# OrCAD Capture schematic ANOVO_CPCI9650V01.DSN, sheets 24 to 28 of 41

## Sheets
24 -IDE slot & COM1 2: size C; title: 24--IDE,CF slot
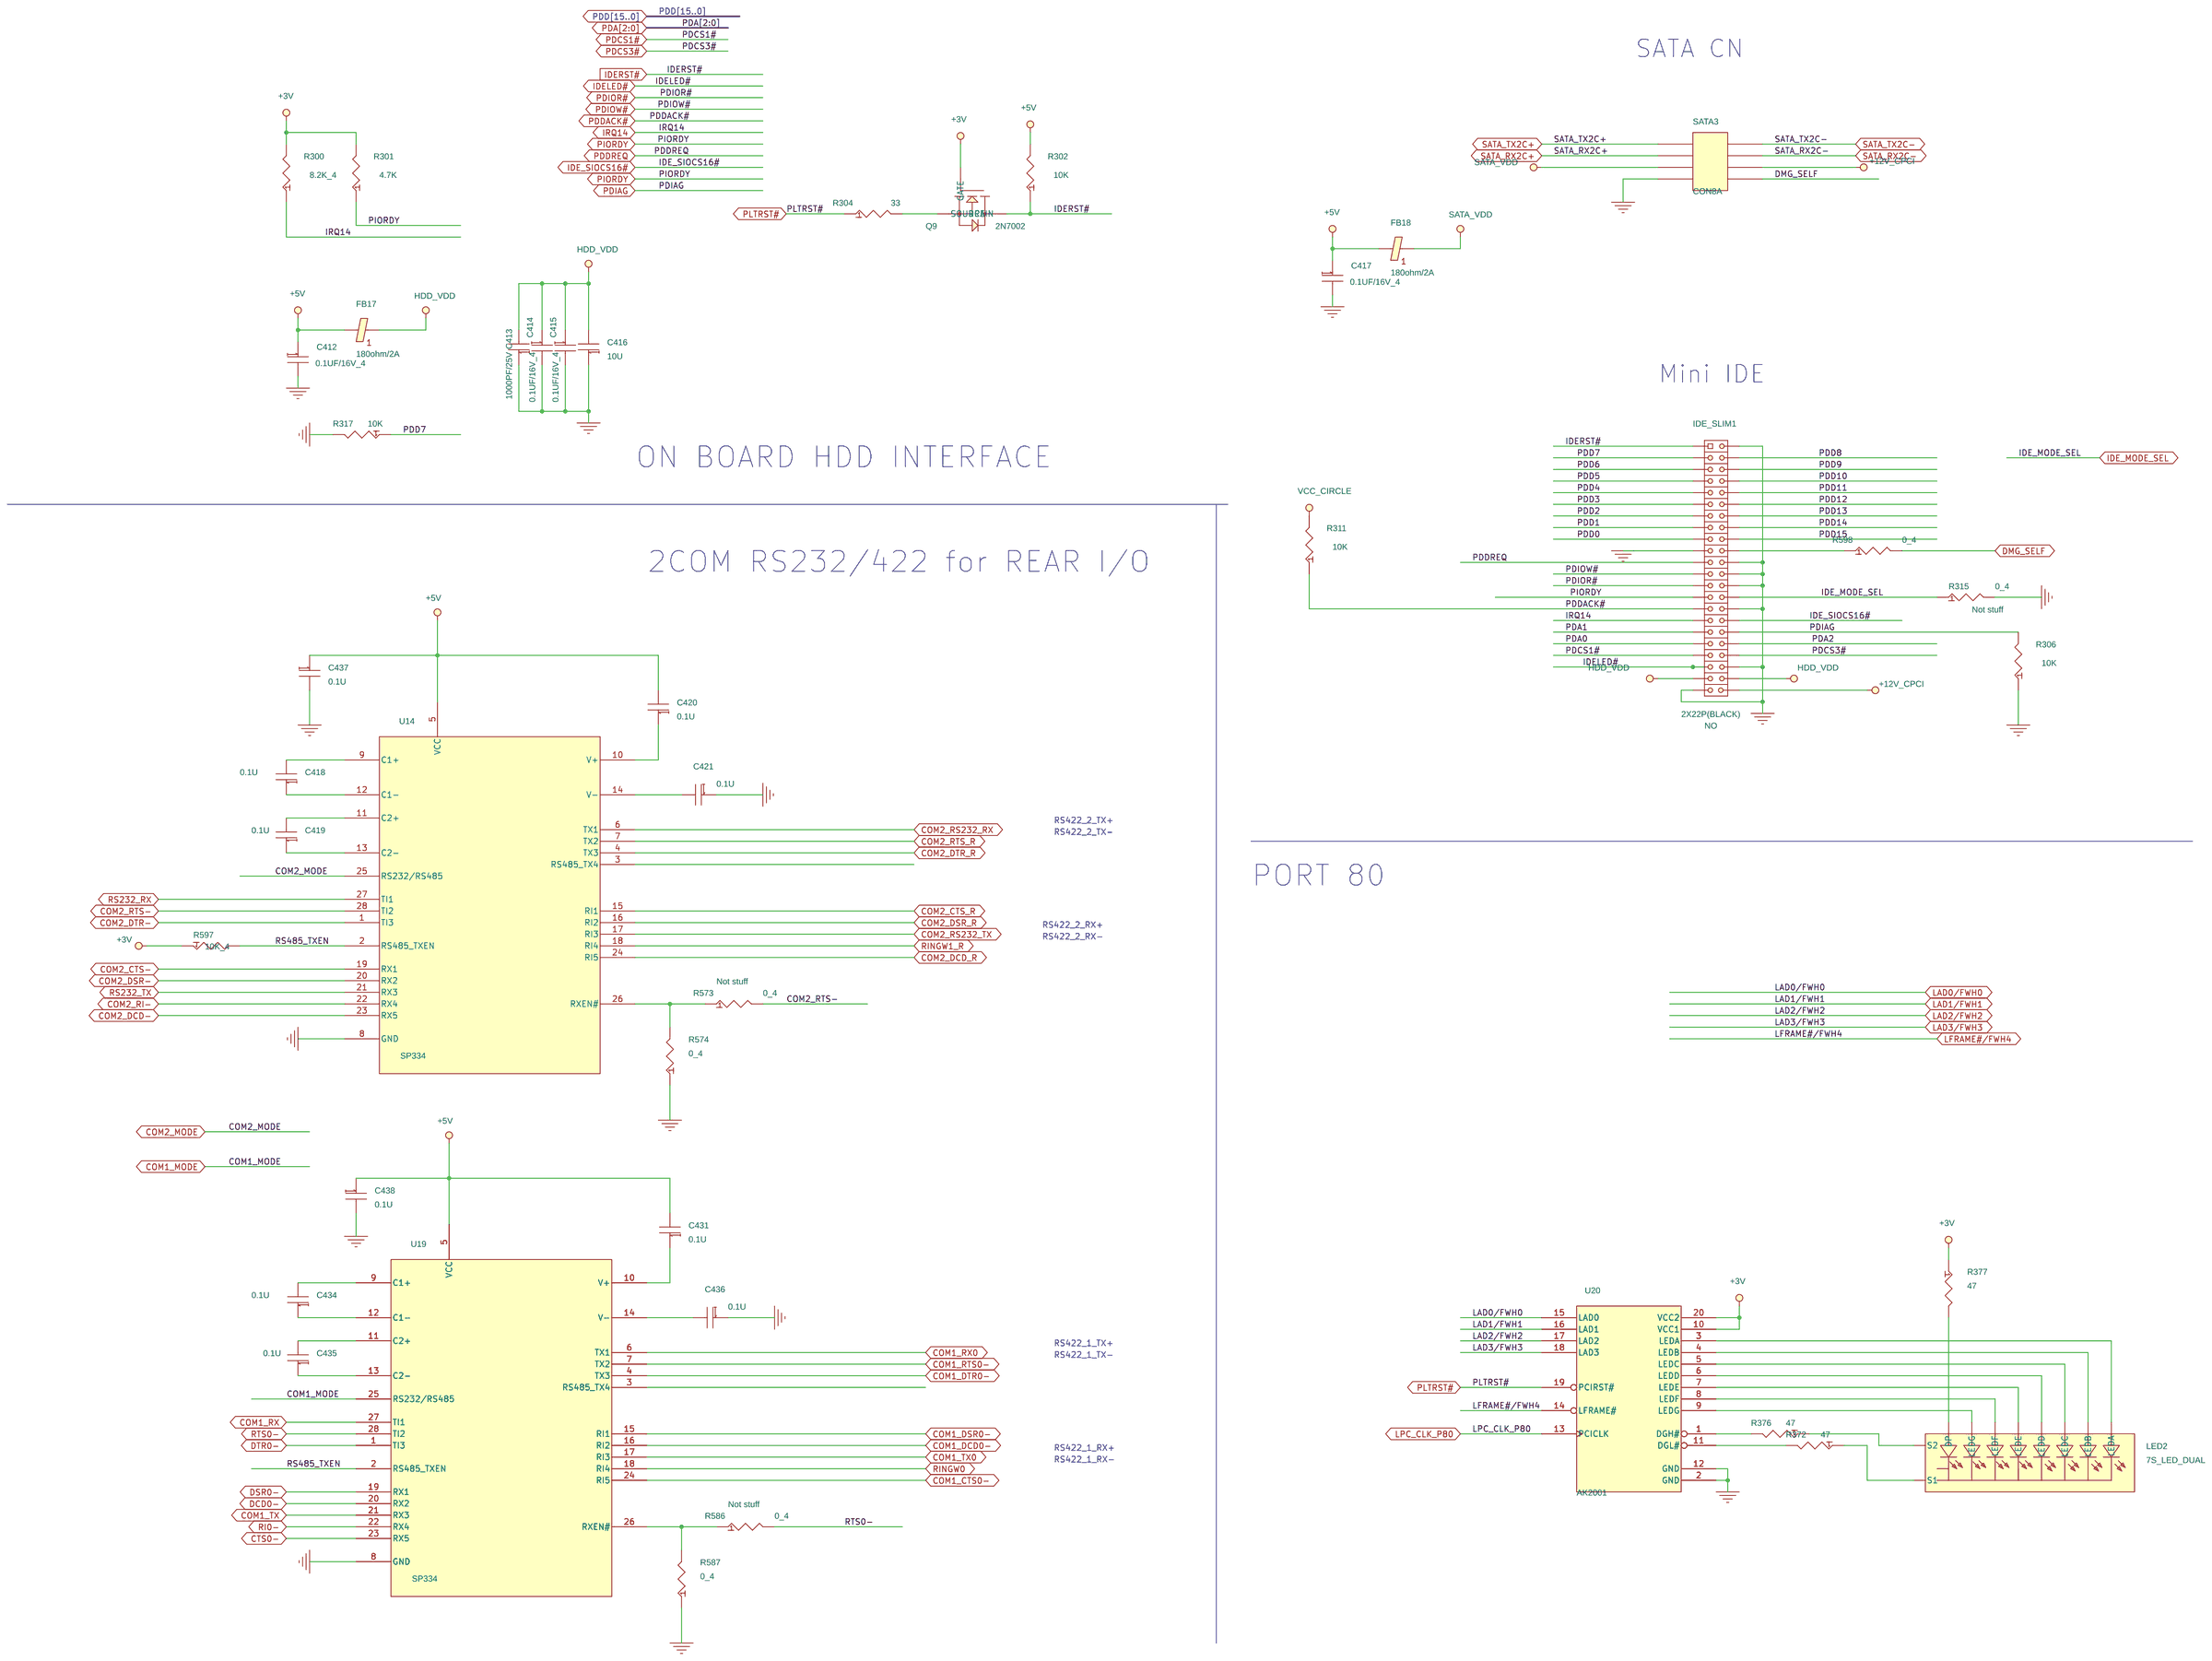
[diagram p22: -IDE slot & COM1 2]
25 -PWRBTN &LVDS VCC: size C; title: 25--SIO_W83627THF
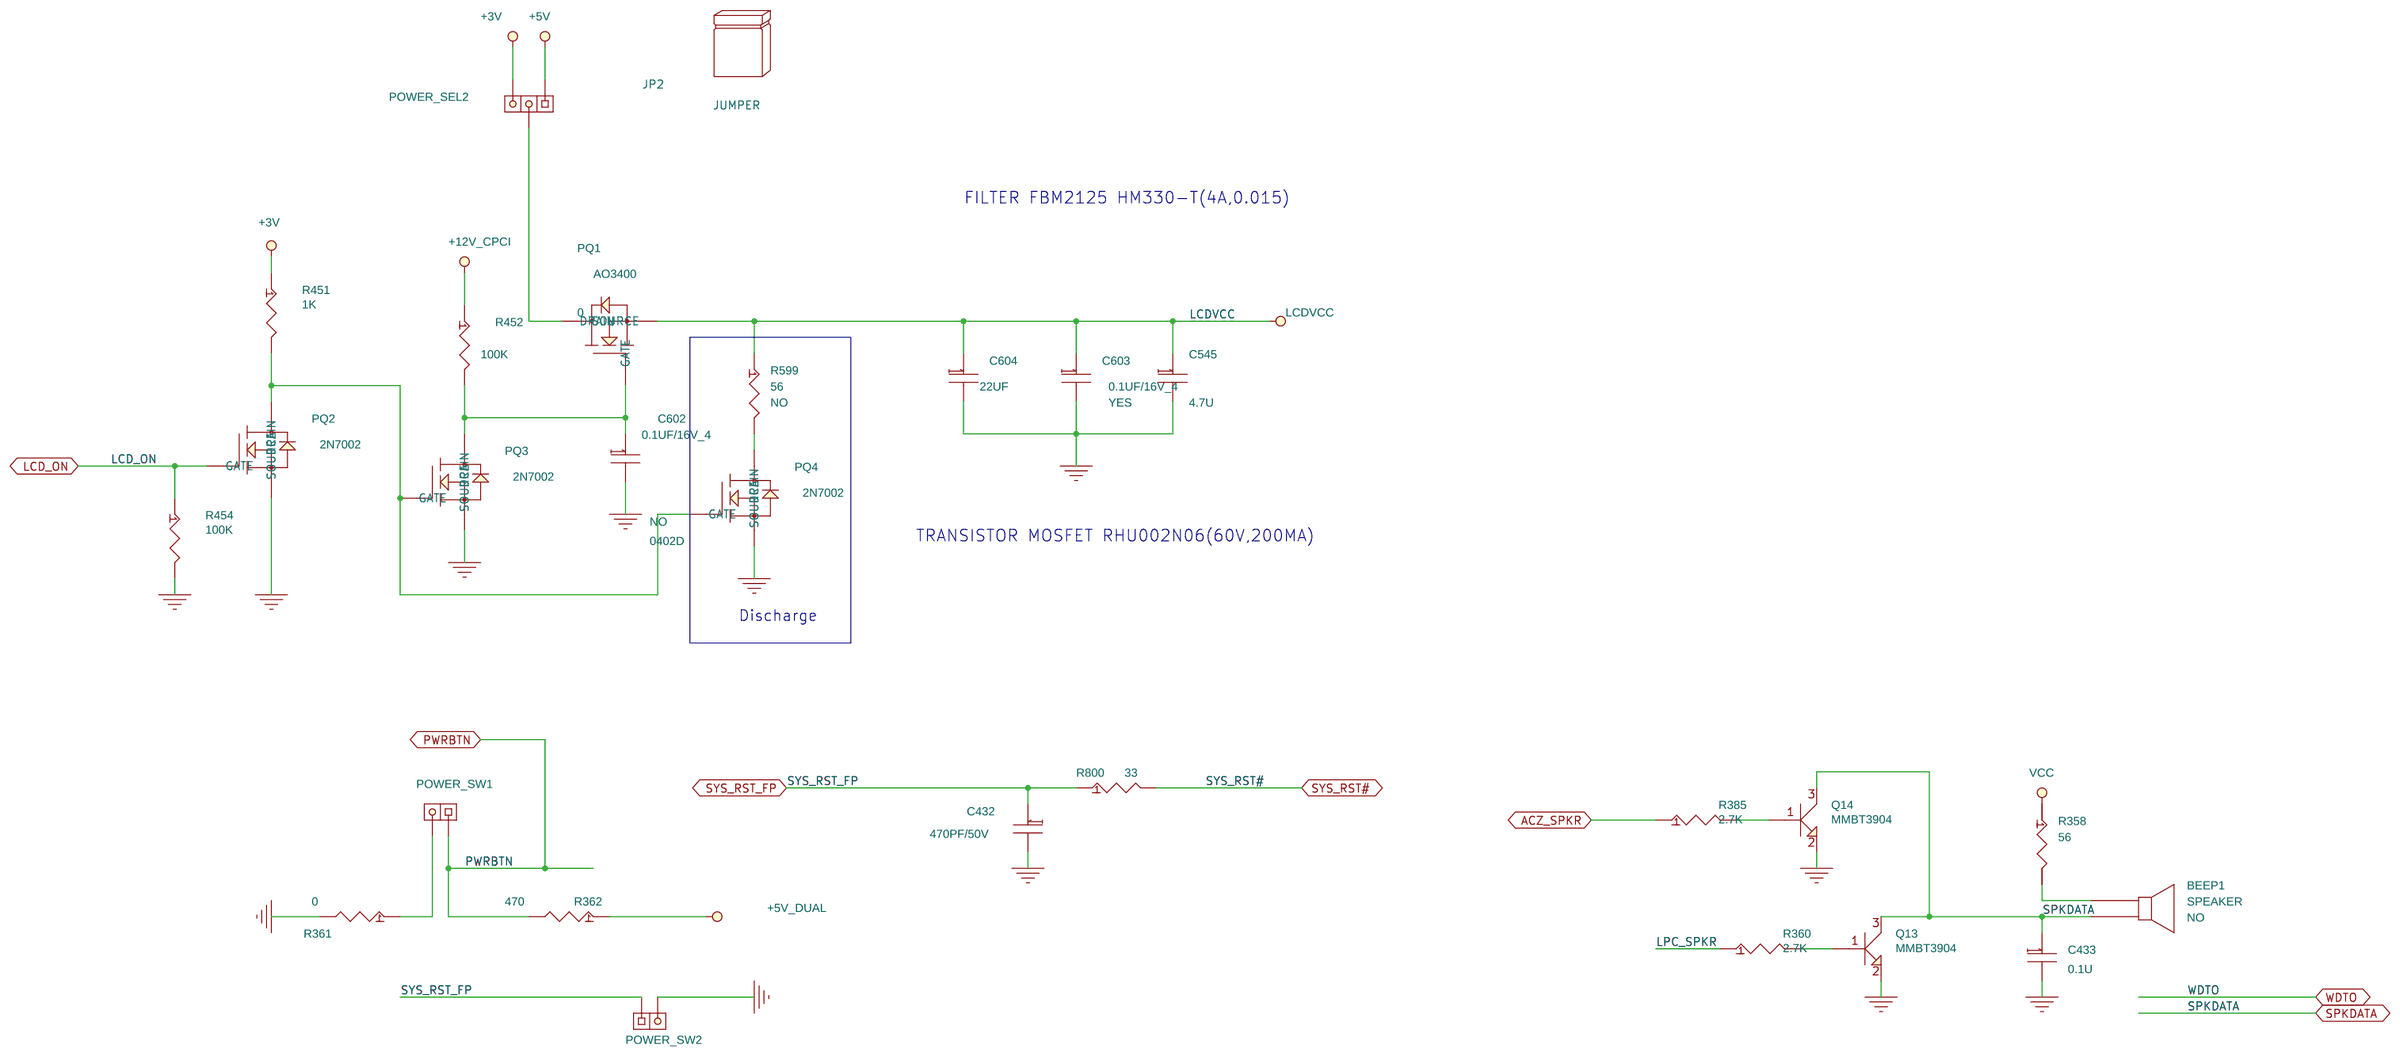
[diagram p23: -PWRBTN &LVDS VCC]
26 -VGA SWITCHS&PIO&WTO: size D; title: 26--VGA swtich&PIO; note: CPCI965
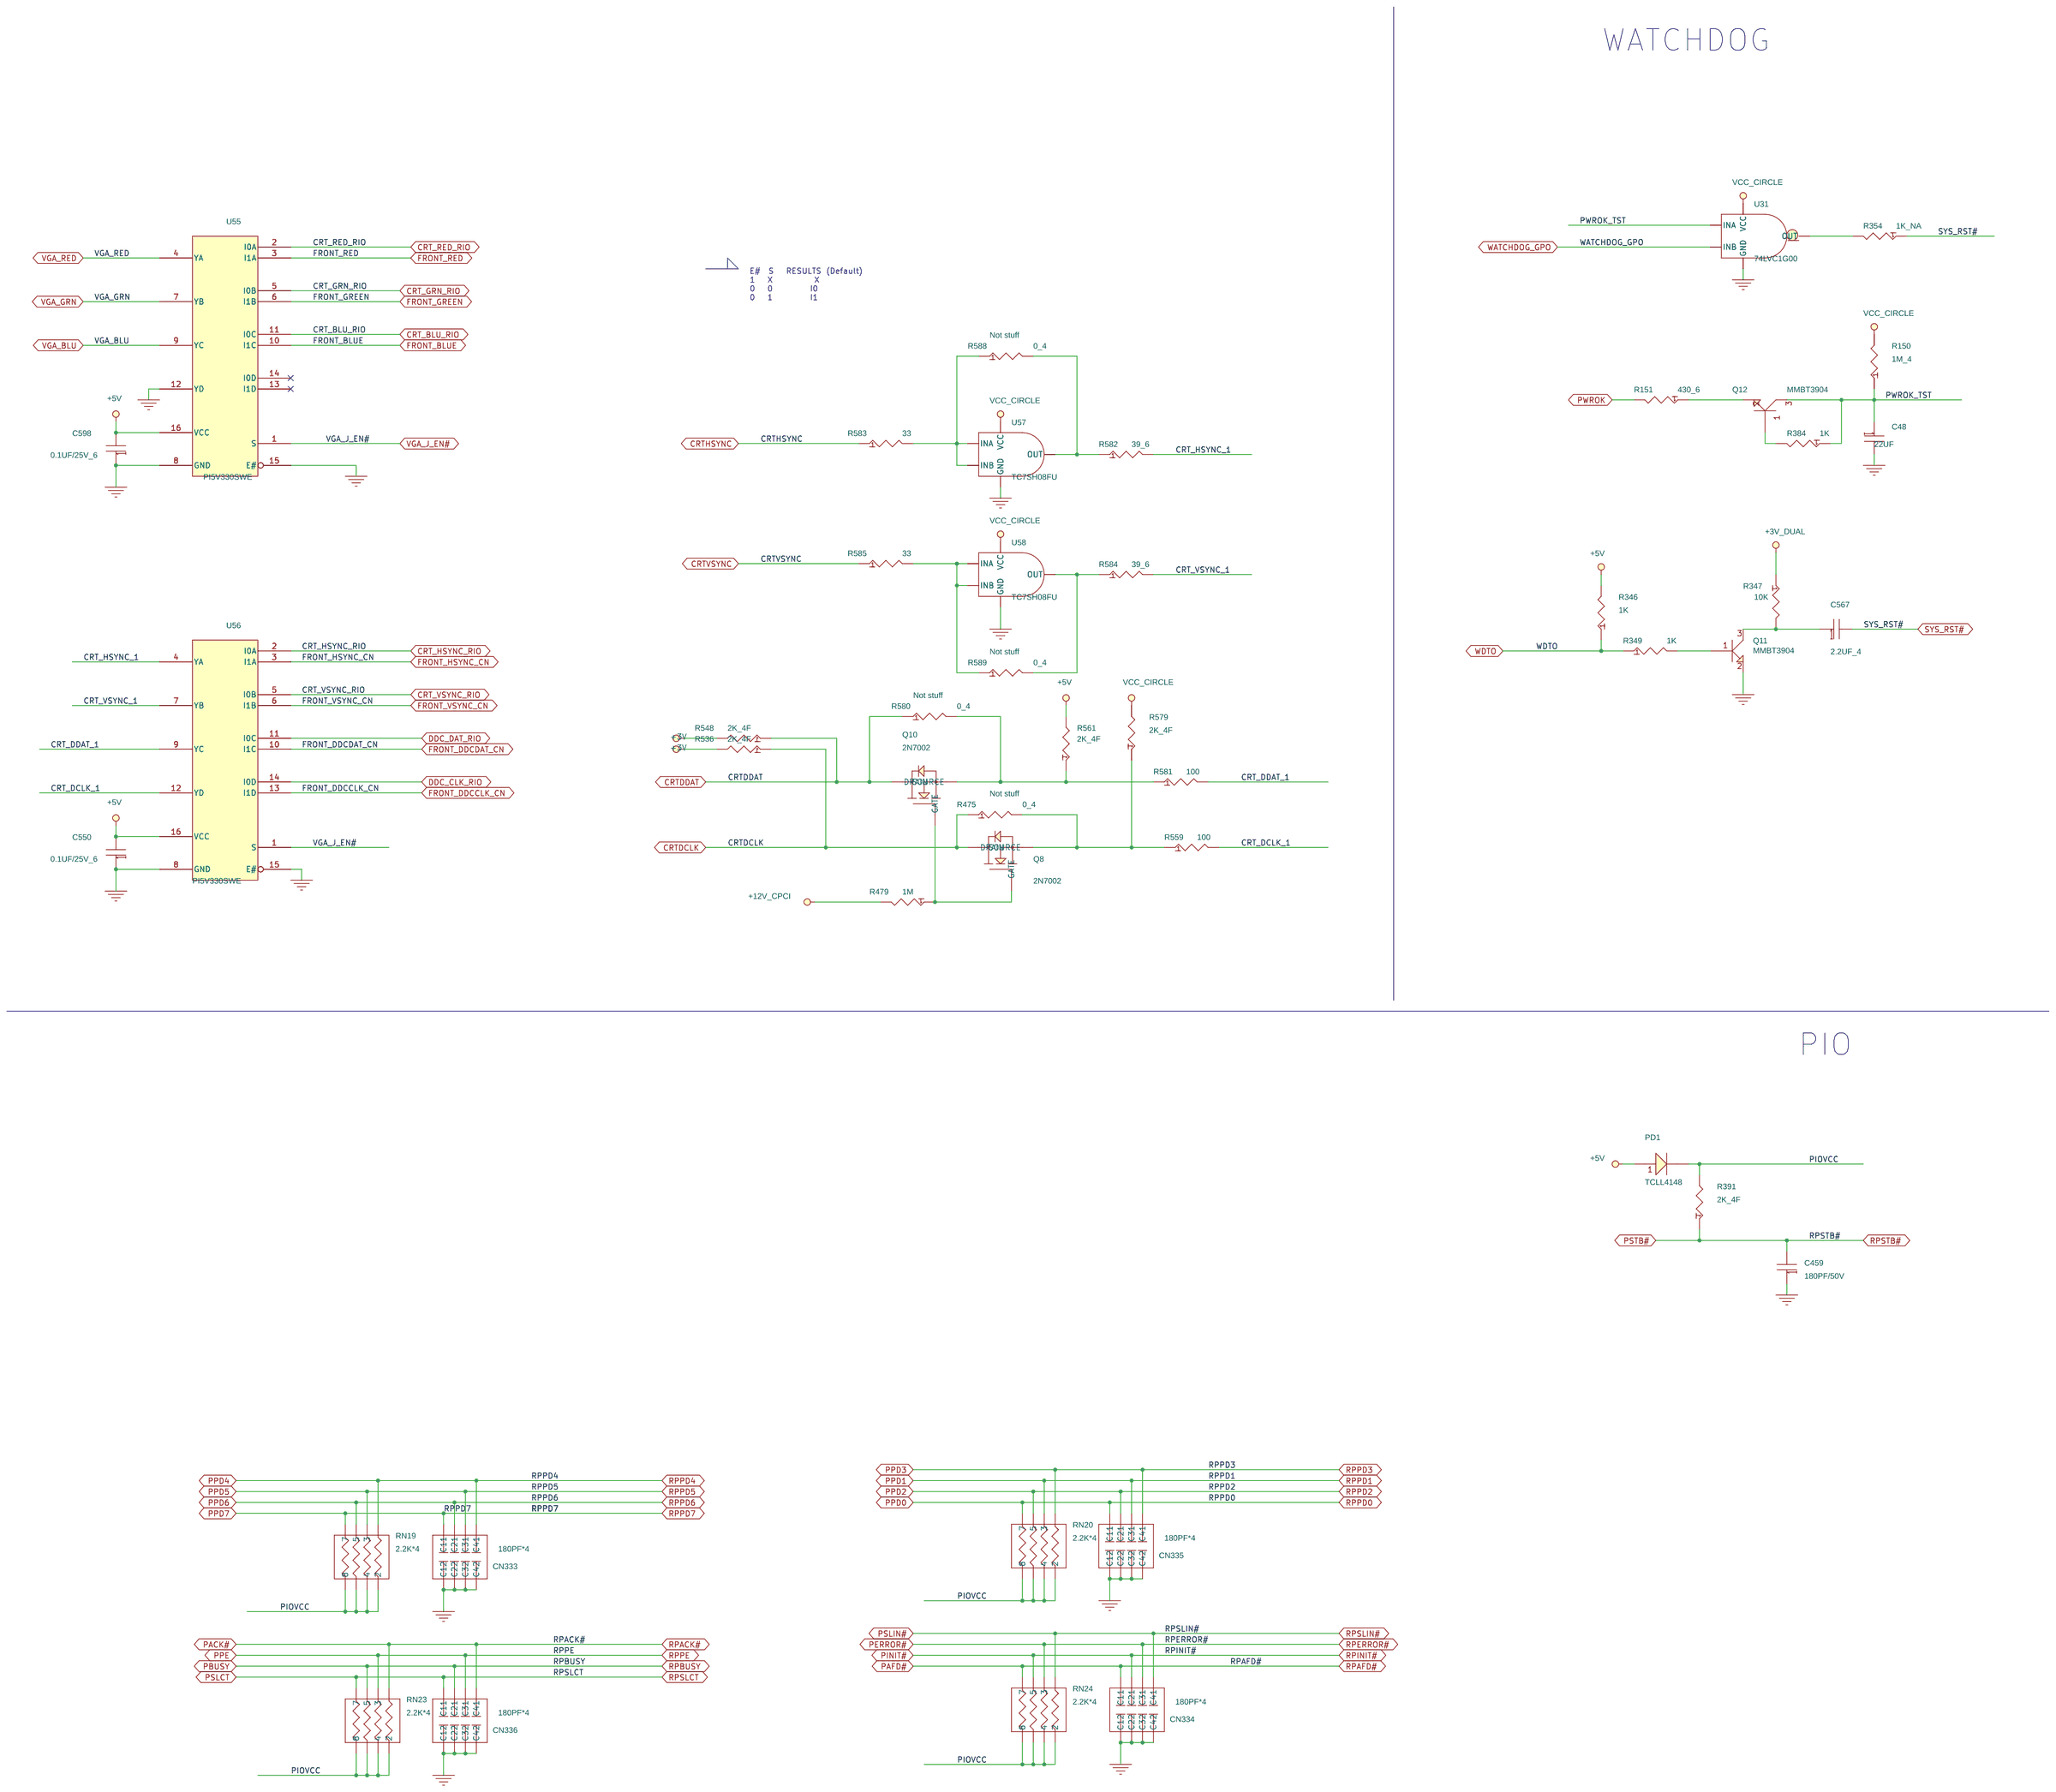
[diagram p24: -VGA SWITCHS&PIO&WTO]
27 -J1 PCI32&BRIDGE: size C; title: 27--J1 PCI32
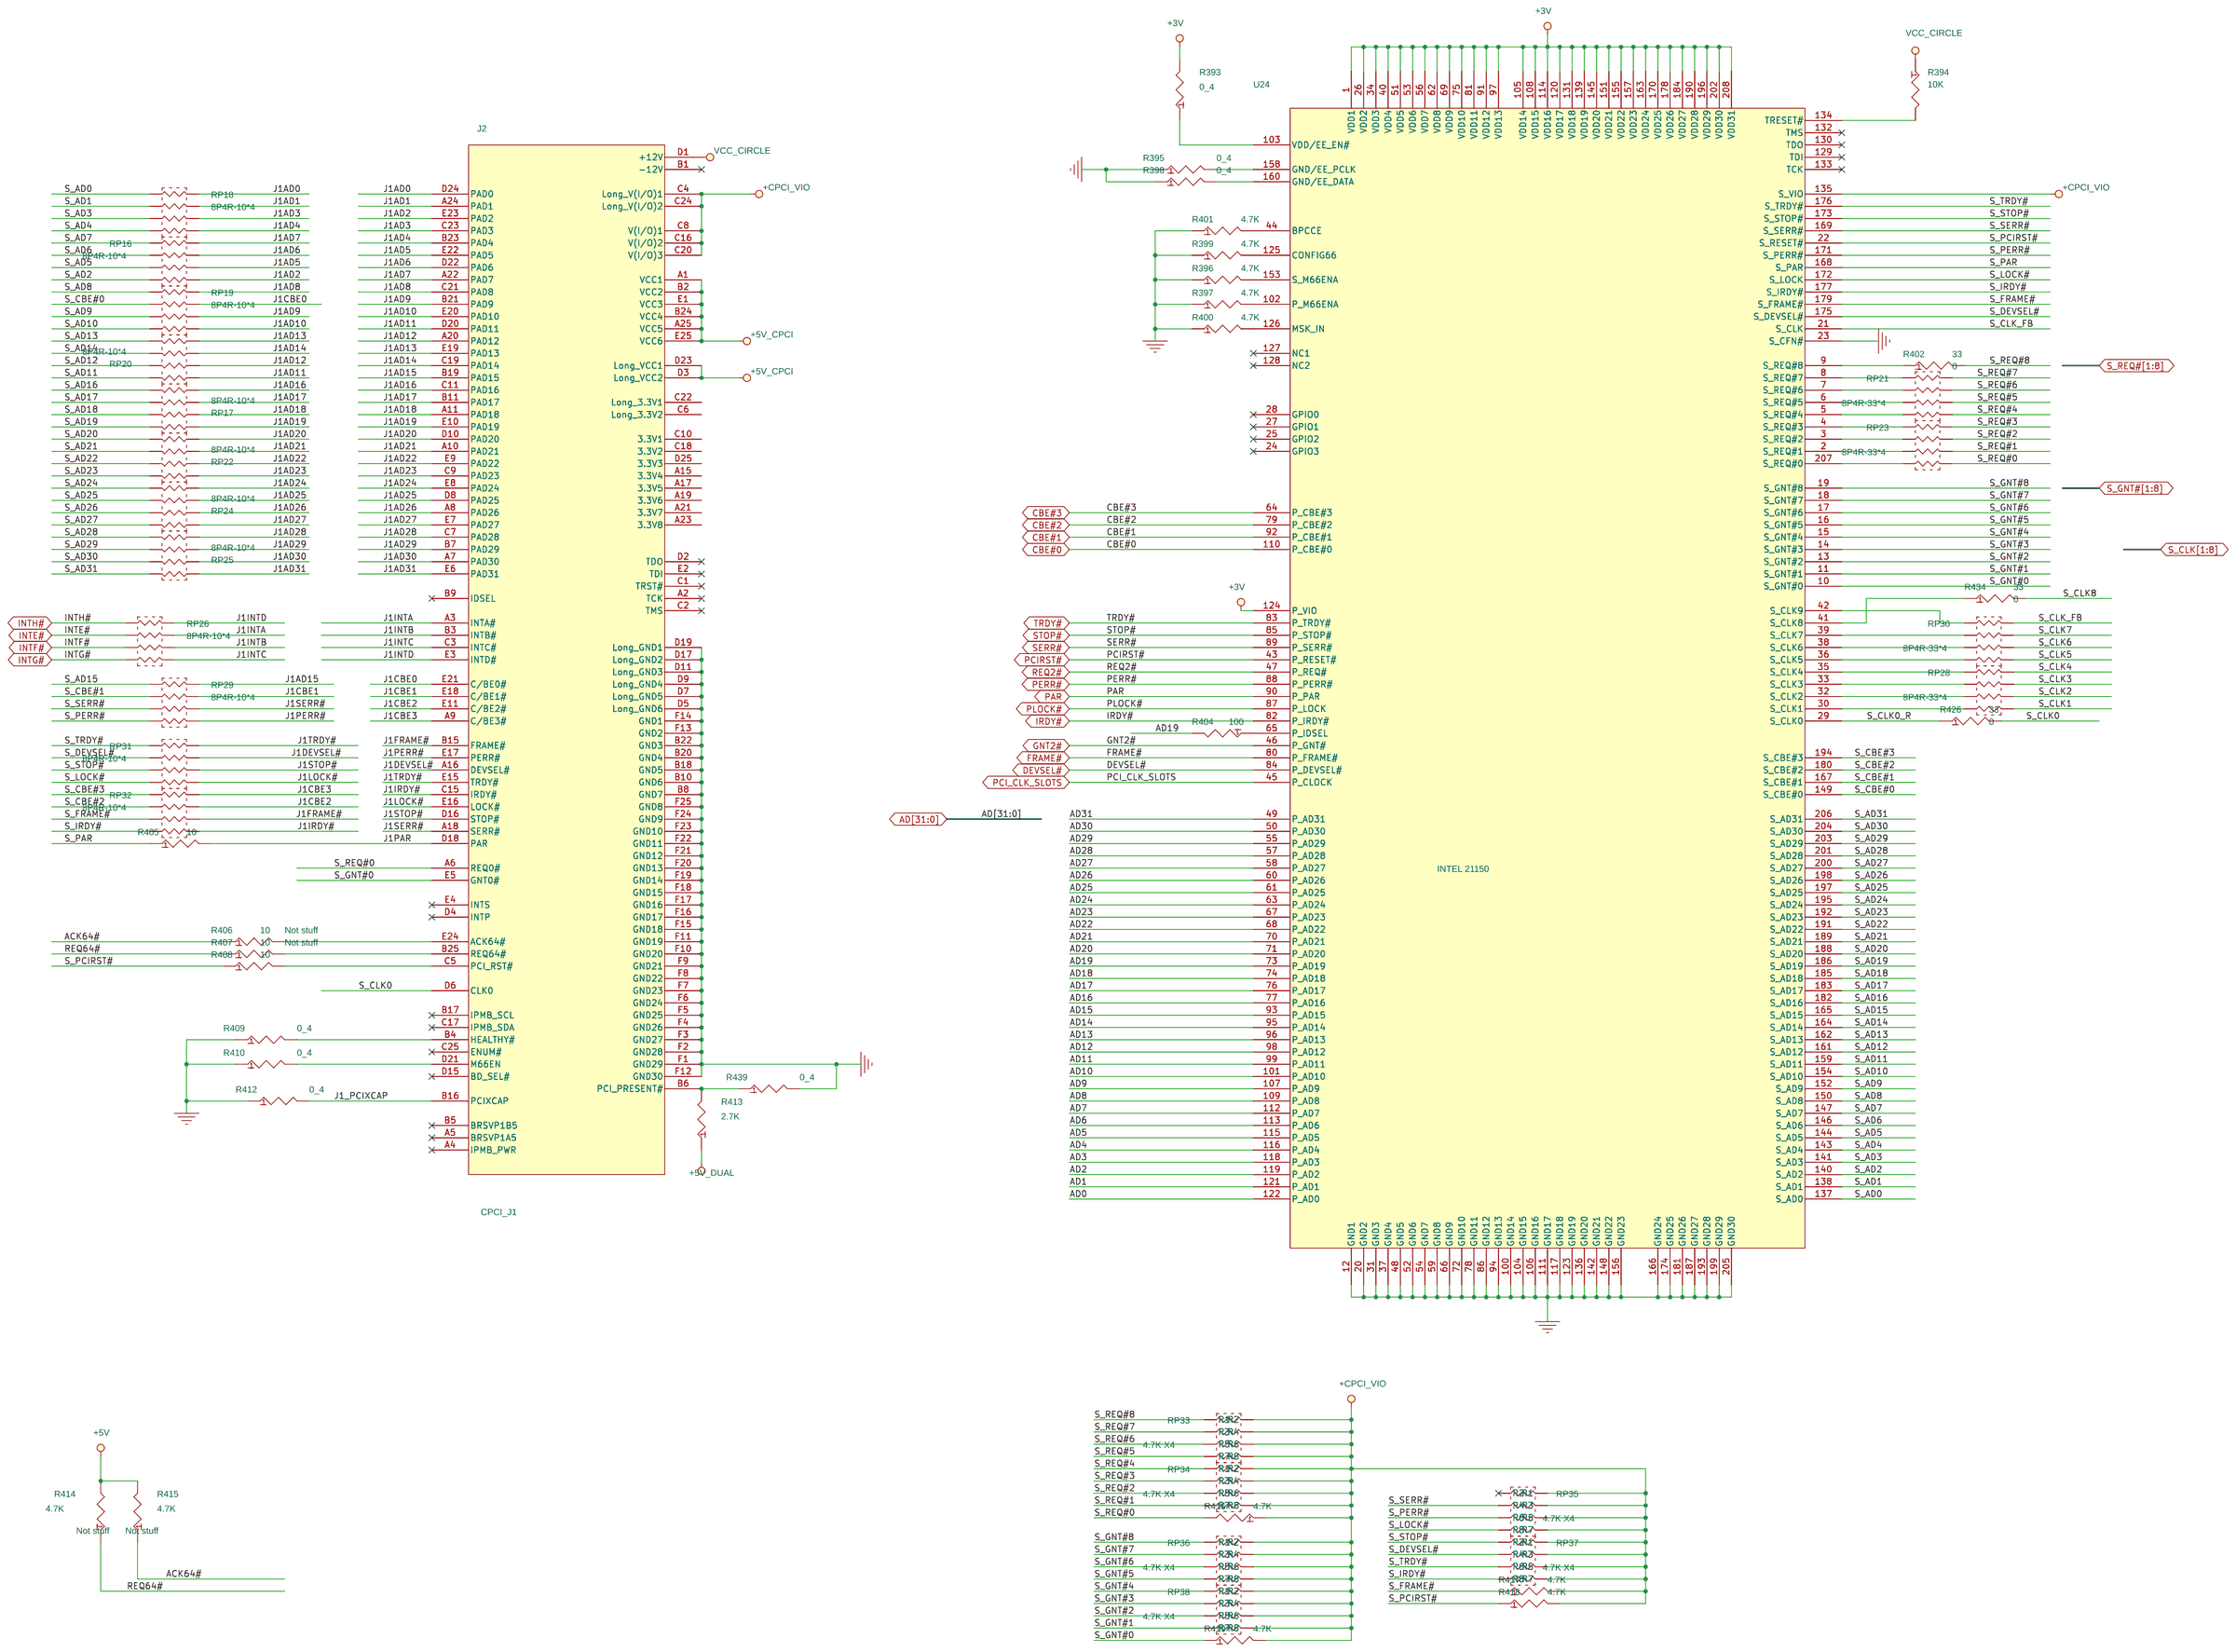
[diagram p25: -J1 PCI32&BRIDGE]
28 -J2 J3 PCIE: size C; title: 28--J2 J3 PCIE
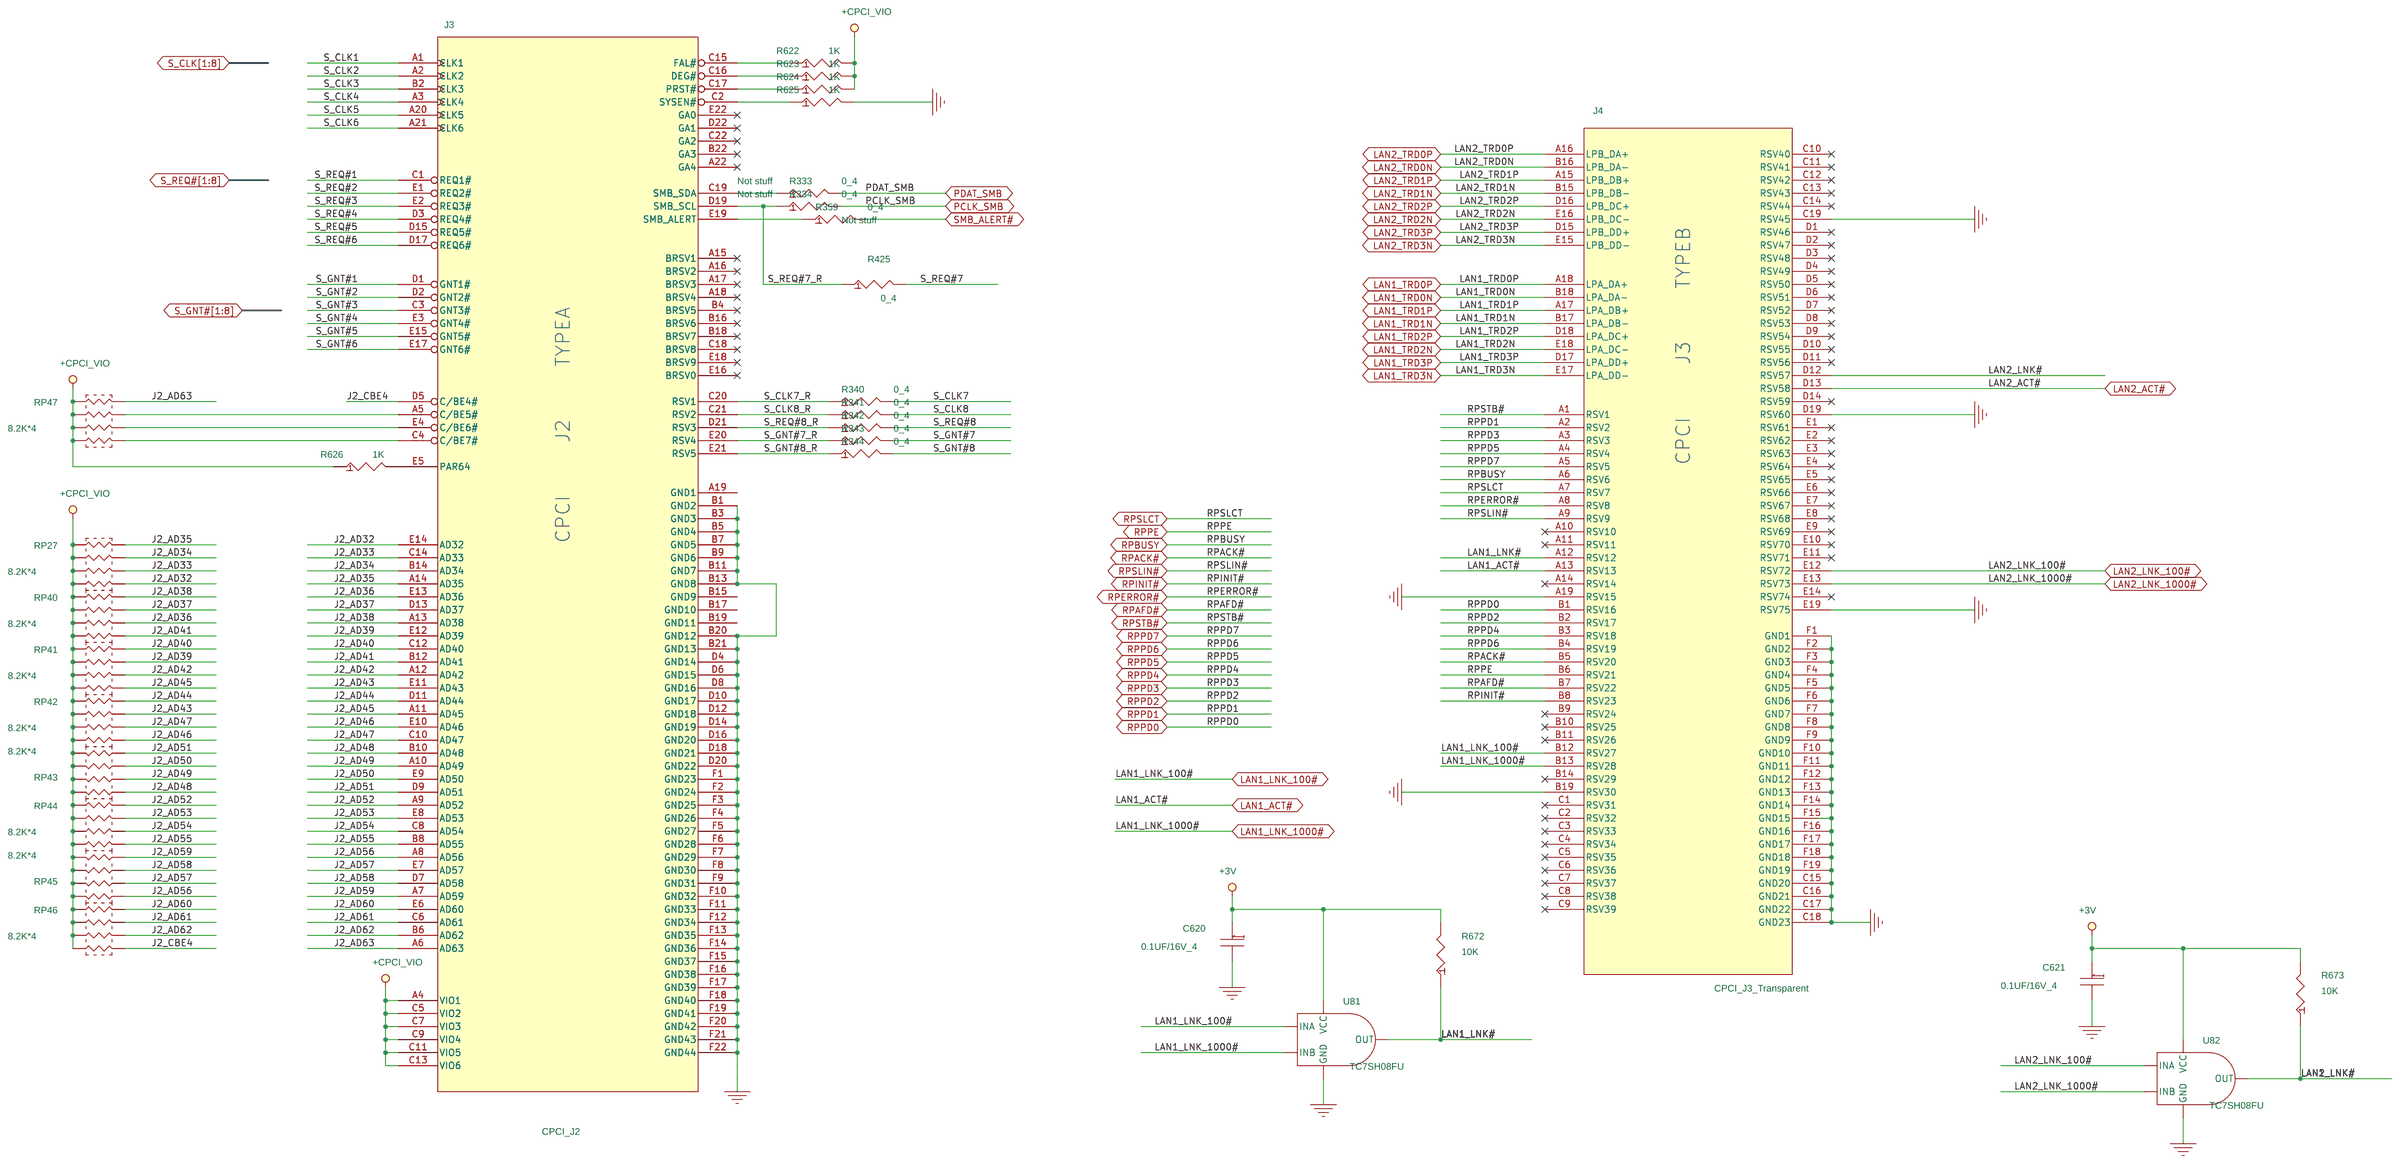
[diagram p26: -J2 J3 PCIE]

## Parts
sheet -IDE slot & COM1 2
C412  0.1UF/16V_4  [0402D]
C413  1000PF/25V  [0402D]
C414  0.1UF/16V_4  [0402D]
C415  0.1UF/16V_4  [0402D]
C416  10U  [0805D]
C417  0.1UF/16V_4  [0402D]
C418  0.1U  [0402D]
C419  0.1U  [0402D]
C420  0.1U  [0402D]
C421  0.1U  [0402D]
C431  0.1U  [0402D]
C434  0.1U  [0402D]
C435  0.1U  [0402D]
C436  0.1U  [0402D]
C437  0.1U  [0402D]
C438  0.1U  [0402D]
FB17  180ohm/2A  [0805D]
FB18  180ohm/2A  [0805D]
IDE_SLIM1  2X22P(BLACK)  [IDE_S]
LED2  7S_LED_DUAL  [LEDX2_2R54X7R62_15X10]
Q9  2N7002  [SOT23N_5]
R300  8.2K_4  [0402D]
R301  4.7K  [0402D]
R302  10K  [0402D]
R304  33  [0402D]
R306  10K  [0402D]
R311  10K  [0402D]
R315  0_4  [0402D]
R317  10K  [0402D]
R372  47  [0603D]
R376  47  [0603D]
R377  47  [0603D]
R573  0_4  [0402D]
R574  0_4  [0402D]
R586  0_4  [0402D]
R587  0_4  [0402D]
R597  10K_4  [0402D]
R598  0_4  [0402D]
SATA3  CON8A  [conn_2x4_2mm]
U14  SP334  [soic_28p_26_706x419]
U19  SP334  [soic_28p_26_706x419]
U20  AK2001  [ssop20_0r64_8r64x5r99]
sheet -J1 PCI32&BRIDGE
J2  CPCI_J1  [conn_cpci25x5_p13]
R393  0_4  [0402D]
R394  10K  [0402D]
R395  0_4  [0402D]
R396  4.7K  [0402D]
R397  4.7K  [0402D]
R398  0_4  [0402D]
R399  4.7K  [0402D]
R400  4.7K  [0402D]
R401  4.7K  [0402D]
R402  33  [0402D]
R404  100  [0402D]
R405  10  [0402D]
R406  10  [0402D]
R407  10  [0402D]
R408  10  [0402D]
R409  0_4  [0402D]
R410  0_4  [0402D]
R412  0_4  [0402D]
R413  2.7K  [0402D]
R414  4.7K  [0402D]
R415  4.7K  [0402D]
R416  4.7K  [0402D]
R417  4.7K  [0402D]
R418  4.7K  [0402D]
R419  4.7K  [0402D]
R426  33  [0402D]
R434  33  [0402D]
R439  0_4  [0402D]
RP16  8P4R-10*4  [RP_8P4R_0804B]
RP17  8P4R-10*4  [RP_8P4R_0804B]
RP18  8P4R-10*4  [RP_8P4R_0804B]
RP19  8P4R-10*4  [RP_8P4R_0804B]
RP20  8P4R-10*4  [RP_8P4R_0804B]
RP21  8P4R-33*4  [RP_8P4R_0804B]
RP22  8P4R-10*4  [RP_8P4R_0804B]
RP23  8P4R-33*4  [RP_8P4R_0804B]
RP24  8P4R-10*4  [RP_8P4R_0804B]
RP25  8P4R-10*4  [RP_8P4R_0804B]
RP26  8P4R-10*4  [RP_8P4R_0804B]
RP28  8P4R-33*4  [RP_8P4R_0804B]
RP29  8P4R-10*4  [RP_8P4R_0804B]
RP30  8P4R-33*4  [RP_8P4R_0804B]
RP31  8P4R-10*4  [RP_8P4R_0804B]
RP32  8P4R-10*4  [RP_8P4R_0804B]
RP33  4.7K X4  [RPSOA_8C]
RP34  4.7K X4  [RPSOA_8C]
RP35  4.7K X4  [RPSOA_8C]
RP36  4.7K X4  [RPSOA_8C]
RP37  4.7K X4  [RPSOA_8C]
RP38  4.7K X4  [RPSOA_8C]
U24  INTEL 21150  [PQFP208A]
sheet -J2 J3 PCIE
C620  0.1UF/16V_4  [0402D]
C621  0.1UF/16V_4  [0402D]
J3  CPCI_J2  [conn_cpci22x5_p11]
J4  CPCI_J3_Transparent  [conn_cpci19x5_p10]
R333  0_4  [0402D]
R334  0_4  [0402D]
R340  0_4  [0402D]
R341  0_4  [0402D]
R342  0_4  [0402D]
R343  0_4  [0402D]
R344  0_4  [0402D]
R359  0_4  [0402D]
R425  0_4  [0402D]
R622  1K  [0402D]
R623  1K  [0402D]
R624  1K  [0402D]
R625  1K  [0402D]
R626  1K  [0402D]
R672  10K  [0402D]
R673  10K  [0402D]
RP27  8.2K*4  [RP_8P4R_0804B]
RP40  8.2K*4  [RP_8P4R_0804B]
RP41  8.2K*4  [RP_8P4R_0804B]
RP42  8.2K*4  [RP_8P4R_0804B]
RP43  8.2K*4  [RP_8P4R_0804B]
RP44  8.2K*4  [RP_8P4R_0804B]
RP45  8.2K*4  [RP_8P4R_0804B]
RP46  8.2K*4  [RP_8P4R_0804B]
RP47  8.2K*4  [RP_8P4R_0804B]
U81  TC7SH08FU  [SSOP5_TOSHIBA]
U82  TC7SH08FU  [SSOP5_TOSHIBA]
sheet -PWRBTN &LVDS VCC
BEEP1  SPEAKER  [BUZ_CB9E]
C432  470PF/50V  [0402D]
C433  0.1U  [0402D]
C545  4.7U  [0805D]
C602  0.1UF/16V_4  [0402D]
C603  0.1UF/16V_4  [0402D]
C604  22UF  [0805D]
JP2  JUMPER
POWER_SEL2  1x3 PIN  [conn_3b]
POWER_SW1  1x2 PIN  [CONN_2B]
POWER_SW2  1x2 PIN  [CONN_2B]
PQ1  AO3400  [SOT23N_5]
PQ2  2N7002  [SOT23N_5]
PQ3  2N7002  [SOT23N_5]
PQ4  2N7002  [SOT23N_5]
Q13  MMBT3904  [SOT23N_5]
Q14  MMBT3904  [SOT23N_5]
R358  56  [0603D]
R360  2.7K  [0402D]
R361  0  [0402D]
R362  470  [0402D]
R385  2.7K  [0402D]
R451  1K  [0402D]
R452  100K  [0402D]
R454  100K  [0402D]
R599  56  [0603D]
R800  33  [0402D]
sheet -VGA SWITCHS&PIO&WTO
C48  22UF  [0805D]
C459  180PF/50V  [0402D]
C550  0.1UF/25V_6  [0603D]
C567  2.2UF_4  [0402D]
C598  0.1UF/25V_6  [0603D]
CN333  180PF*4  [RPSOA_8D]
CN334  180PF*4  [RPSOA_8D]
CN335  180PF*4  [RPSOA_8D]
CN336  180PF*4  [RPSOA_8D]
PD1  TCLL4148  [DC1506N]
Q8  2N7002  [SOT23N_5]
Q10  2N7002  [SOT23N_5]
Q11  MMBT3904  [SOT23N_5]
Q12  MMBT3904  [SOT23N_5]
R150  1M_4  [0402D]
R151  430_6  [0603D]
R346  1K  [0402D]
R347  10K  [0402D]
R349  1K  [0402D]
R354  1K_NA  [0402D]
R384  1K  [0402D]
R391  2K_4F  [0402D]
R475  0_4  [0402D]
R479  1M  [0603D]
R536  2K_4F  [0402D]
R548  2K_4F  [0402D]
R559  100  [0402D]
R561  2K_4F  [0402D]
R579  2K_4F  [0402D]
R580  0_4  [0402D]
R581  100  [0402D]
R582  39_6  [0603D]
R583  33  [0402D]
R584  39_6  [0603D]
R585  33  [0402D]
R588  0_4  [0402D]
R589  0_4  [0402D]
RN19  2.2K*4  [RPSOA_8C]
RN20  2.2K*4  [RPSOA_8C]
RN23  2.2K*4  [RPSOA_8C]
RN24  2.2K*4  [RPSOA_8C]
U31  74LVC1G00  [SSOP5_TOSHIBA]
U55  PI5V330SWE  [SOIC16]
U56  PI5V330SWE  [SOIC16]
U57  TC7SH08FU  [SSOP5_TOSHIBA]
U58  TC7SH08FU  [SSOP5_TOSHIBA]

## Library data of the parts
C412 C414 C415 C417 C620 C621 = CAP_NP: ANOVO DESCRIPTION: CAP;0.1U ,16V ,+80-20% ,0402 ,Y5V ,SMT; ANOVO PART NUMBER: 272043104401; BACKSIDE: 0; Part Type: CCAP; SMT: YES
C413 = CAP_NP: ANOVO DESCRIPTION: CAP;1000P ,16V ,10% ,0402 ,X7R ,SMT; ANOVO PART NUMBER: 272043102201; BACKSIDE: 0; Part Type: CCAP
C416 = CAP_NP: ANOVO DESCRIPTION: CAP;10U,10V,+80-20%,0805,Y5V,SMT; ANOVO PART NUMBER: 272002106401; Part Type: CCAP
C418-C421 C431 C433-C438 = CAP_NP: ANOVO DESCRIPTION: CAP;0.1U ,16V ,10% ,0402 ,X7R ,SMT; ANOVO PART NUMBER: 272043104201; Part Type: CCAP
FB17 FB18 = FERRITE_BEAD: ANOVO DESCRIPTION: FERRITE CHIP;180 OHM/100MHZ,2A,0805,SMT; ANOVO PART NUMBER: 273001814300; BACKSIDE: 0; Part Type: FERRITE BEAD; SMT: YES
IDE_SLIM1 = HEADER_2X20_0: ANOVO DESCRIPTION: CON,DIP,HDR,W/Shield,Black,22P*2,2.00*2.00mm pitch,ST,Slim IDE,Gold,Lotes; ANOVO PART NUMBER: 331120044100; BACKCOMP: NO; BACKSIDE: NO; Part Number: 131000064; Part Type: HEADER; ROOM: IDE; SMT: NO
LED2 = 7Seg_LED_0: ANOVO DESCRIPTION: CON;DIP,DISPLAY MODULE,7SEG,0.28INCH,GREEN,COMMON CATHODE,BD-F282RD,LIGITEK; ANOVO PART NUMBER: 331520010000
PQ2-PQ4 Q8-Q10 = MOSFET_N_3P: ANOVO DESCRIPTION: TRANS;2N7002,N-MOSFET,60V,500mA,SOT23; ANOVO PART NUMBER: 288227002001; BACKSIDE: 0; Part Type: MOSFET; SMT: YES
R300 = R_v2: ANOVO DESCRIPTION: RES;8.2K ,1/16W ,5% ,0402 ,SMT; ANOVO PART NUMBER: 271040822301; BACKSIDE: 0; Part Type: RESISTOR; SMT: YES
R301 R396 R397 R399-R401 R416-R419 = R_v2: ANOVO DESCRIPTION: RES;4.7K ,1/16W ,5% ,0402 ,SMT; ANOVO PART NUMBER: 271040472301; Part Type: RESISTOR
R302 R306 R311 R317 R347 R672 R673 = R_v2: ANOVO DESCRIPTION: RES;10K ,1/16W ,5% ,0402 ,SMT; ANOVO PART NUMBER: 271040103301; BACKSIDE: 0; Part Type: RESISTOR; SMT: YES
R304 R402 R426 R434 R583 R585 = R_v2: ANOVO DESCRIPTION: RES;33 ,1/16W ,5% ,0402 ,SMT; ANOVO PART NUMBER: 271040330301; BACKSIDE: 0; Part Type: RESISTOR; SMT: YES
R315 R573 R586 = R_v2: ANOVO DESCRIPTION: RES;0 ,1/16W ,5% ,0402 ,SMT; ANOVO PART NUMBER: 271040000301; DUMMY: Not stuff; Part Type: RESISTOR; SMT: YES
R372 R376 R377 = R_v2: RES;47 ,1/10W ,1% ,0603 ,SMT; ANOVO DESCRIPTION: RES;47 ,1/10W ,1% ,0603 ,SMT; ANOVO PART NUMBER: 271071470101; BACKCOMP: YES; Part Type: RESISTOR; SMT: YES
R361 R393 R409 R410 R412 R439 R574 R587 R598 = R_v2: ANOVO DESCRIPTION: RES;0 ,1/16W ,5% ,0402 ,SMT; ANOVO PART NUMBER: 271040000301; Part Type: RESISTOR; SMT: YES
R597 = R_v2: ANOVO DESCRIPTION: RES;10K ,1/16W ,5% ,0402 ,SMT; ANOVO PART NUMBER: 271040103301
SATA3 = CON8A: ANOVO DESCRIPTION: CON;DIP;HDR;4P*2;2.00mm pitch;ST;Gold;Zhiwei; ANOVO PART NUMBER: 331020008100
U14 U19 = SP334_1
U20 = IC-AK2001: ANOVO DESCRIPTION: IC;AK2001,TIMER,260'C,SSOP,20P; ANOVO PART NUMBER: 286302001001
J2 = CPCI_J1_PCI32_5: Conn. 5x25P 2.0mm 90D(F) Type A; ANOVO DESCRIPTION: CON;Press Header;femaW/shield;Yellow;110 /123Pins;5ROWS;2.00mm;R/A;CPCI Type A,(J1/J4)5352068-1,TYCO; ANOVO PART NUMBER: 333150110002
R394 = R_v2: res 10kh 0603 1/16w +-5%; ANOVO DESCRIPTION: RES;10K ,1/16W ,5% ,0402 ,SMT; ANOVO PART NUMBER: 271040103301; BACKCOMP: YES; BACKSIDE: YES; ID: 60; Part Number: 138000033; Part Type: RESISTOR; Power: 1/16w; SMT: YES
R395 R398 = R_v2: ANOVO DESCRIPTION: RES;0 ,1/16W ,5% ,0402 ,SMT; ANOVO PART NUMBER: 271040000301; BACKCOMP: YES; BACKSIDE: YES; ID: 0; Part Type: RESISTOR; SMT: YES
R404 = R_v2: ANOVO DESCRIPTION: RES;100 ,1/16W ,1% ,0402 ,SMT; ANOVO PART NUMBER: 271040101101; Part Type: RESISTOR
R405 R408 = R_v2: ANOVO DESCRIPTION: RES;10 ,1/16W ,5% ,0402 ,SMT; ANOVO PART NUMBER: 271040100301; Part Type: RESISTOR; SMT: YES
R406 R407 = R_v2: ANOVO DESCRIPTION: RES;10 ,1/16W ,5% ,0402 ,SMT; ANOVO PART NUMBER: 271040100301; DUMMY: Not stuff; Part Type: RESISTOR; SMT: YES
R360 R385 R413 = R_v2: ANOVO DESCRIPTION: RES;2.7K ,1/16W ,5% ,0402 ,SMT; ANOVO PART NUMBER: 271040272301; Part Type: RESISTOR; SMT: YES
R414 R415 = R_v2: ANOVO DESCRIPTION: RES;4.7K ,1/16W ,5% ,0402 ,SMT; ANOVO PART NUMBER: 271040472301; DUMMY: Not stuff; Part Type: RESISTOR
RP16-RP20 RP22 RP24-RP26 RP29 RP31 RP32 = 10*4_1: RP,10*4 ,8P ,1/16W ,5% 0408 ,SMT; ANOVO DESCRIPTION: RP,10*4 ,8P ,1/16W ,5% 0408 ,SMT; ANOVO PART NUMBER: 271590100301
RP21 RP23 RP28 RP30 = 10*4_2: RP;33*4 ,8P ,1/16W ,5% ,0408,SMT; ANOVO DESCRIPTION: RP;33*4 ,8P ,1/16W ,5% ,0408,SMT; ANOVO PART NUMBER: 271590330301
RP33-RP38 = 10*4_4: ANOVO DESCRIPTION: RP;4.7K*4 ,8P ,1/16W ,5% ,0612 ,SMT; ANOVO PART NUMBER: 271610472301
U24 = INTEL21150_0: ANOVO DESCRIPTION: IC;PI7C8150BMA-33,PCI Bridge,1to9,FQFP-208,Pericom; ANOVO PART NUMBER: 286308150001
J3 = CPCI_J2_15: ANOVO DESCRIPTION: CON;Press Header;female;W/shield;Yellow;110/121 Pins;5 ROWS;2.00mm;R/A;CPCI Type B,5352152-4,TYCO; ANOVO PART NUMBER: 333150110001
J4 = CPCI_J3_Transparent_7: ANOVO DESCRIPTION: CON;Press Header;female;W/shield;Yellow;95/105 Pins;5 ROWS;2.00mm;R/A;CPCI Type B£¬5352171-1,TYCO; ANOVO PART NUMBER: 333150095000
R333 R334 R359 = R_v2: ANOVO DESCRIPTION: RES;0 ,1/16W ,5% ,0402 ,SMT; ANOVO PART NUMBER: 271040000301; DUMMY: Not stuff; ID: 42; Part Type: RESISTOR; SMT: YES
R340-R344 R425 = R_v2: ANOVO DESCRIPTION: RES;0 ,1/16W ,5% ,0402 ,SMT; ANOVO PART NUMBER: 271040000301; ID: 42; Part Type: RESISTOR; SMT: YES
R346 R349 R354 R384 R451 R622-R626 = R_v2: ANOVO DESCRIPTION: RES;1K ,1/16W ,1% ,0402 ,SMT; ANOVO PART NUMBER: 271040102101; Part Type: RESISTOR
RP27 RP40-RP47 = 10*4_2: RP;33*4 ,8P ,1/16W ,5% ,0408,SMT; ANOVO DESCRIPTION: RP;8.2K*4 ,8P ,1/16W ,5% ,0408,SMT; ANOVO PART NUMBER: 271590822301
U57 U58 U81 U82 = TC7SH08FU
BEEP1 = SPEAKER: SPEAKER SOUND 2.4KHZ FREG.THT.; ANOVO DESCRIPTION: BUZZER;DIP;AC5V;D9mm,H4mm;P4mm; ANOVO PART NUMBER: 335100904010; BACKCOMP: NO; BACKSIDE: NO; Part Number: 153000000; SMT: NO
C432 = CAP_NP: ANOVO DESCRIPTION: CAP;470P ,50V ,10% ,0402 ,X7R ,SMT; ANOVO PART NUMBER: 272045471201; BACKSIDE: 0; Part Type: CCAP
C545 = CAP_NP: ANOVO DESCRIPTION: CAP;4.7U ,10V ,+80-20% ,0805 ,Y5V ,SMT; ANOVO PART NUMBER: 272002475401; Part Type: CCAP
C602 = CAP_NP: ANOVO DESCRIPTION: CAP;0.1U ,16V ,+80-20% ,0402 ,Y5V ,SMT; ANOVO PART NUMBER: 272043104401; BACKCOMP: NO; BACKSIDE: NO; Distributor: YANGJUN; ID: 15; Part Number: 1330000180; Part Type: CCAP; Power: 25V/50V; SMT: YES
C603 = CAP_NP: ANOVO DESCRIPTION: CAP;0.1U ,16V ,+80-20% ,0402 ,Y5V ,SMT; ANOVO PART NUMBER: 272043104401; BACKCOMP: YES; BACKSIDE: YES; Distributor: YANGJUN; ID: 15; Part Number: 1330000180; Part Type: CCAP; Power: 25V/50V; SMT: YES
C48 C604 = CAP_NP: ANOVO DESCRIPTION: CAP,22U ,CR,16V ,+80-20%,0805,Y5V,SMT,TAIYO; ANOVO PART NUMBER: 272003226401; BACKSIDE: 0; Part Type: CCAP; SMT: YES
JP2 = JUMPER: JUMPER COLOR BULE A TYPE; ANOVO DESCRIPTION: Jumper;Black;Plastic;2.54mm;Lotes; ANOVO PART NUMBER: 342700254000; Date: 00-12-5; Device: 143000000; ID: 172; Part Number: 143000000; Part Type: attachment; ROOM: USEATX; SMT: NO
POWER_SEL2 = HEADER_1x3: header 1x3 pin; ANOVO DESCRIPTION: CON;DIP;HDR;3P*1;2.54mm pitch;ST;Gold;Zhiwei; ANOVO PART NUMBER: 331010003000; Device: 131000001; Part Number: 131000001; ROOM: USEATX; SMT: NO
POWER_SW1 POWER_SW2 = HEADER_1x2: ANOVO DESCRIPTION: CON;DIP;HDR;2P*1;2.54mm pitch;ST;Gold;Zhiwei; ANOVO PART NUMBER: 331010002000
PQ1 = MOSFET_N_3P: MOSFET FDN335N 1.7A/20V SMT FAIRCHILD; ANOVO DESCRIPTION: TRANS;AO3400,N-MOSFET,30V,5.8A,28MOHM,SOT23,A&O; ANOVO PART NUMBER: 288223400001; BACKCOMP: NO; BACKSIDE: 0; Distributor: Han Dongfeng; Part Number: 126000041; Part Type: MOSFET; SMT: YES; SYM_MIRROR: NO; Datasheet: \\Rdserver\norcocis\datasheet\MOSFET\FAIRCHILD\FDN335N.pdf
Q11-Q14 = NPN: ANOVO DESCRIPTION: TRANS;MMBT3904,NPN,40V,200mA,SOT23; ANOVO PART NUMBER: 288203904001; BACKSIDE: 0; Part Type: TRANSISTOR; SMT: YES; Datasheet: \\Rdserver\norcocis\datasheet\transistor\fairchild\MMBT3904.pdf
R358 = R_v2: ANOVO DESCRIPTION: RES;56 ,1/10W ,5% ,0603 ,SMT; ANOVO PART NUMBER: 271071560301; BACKSIDE: 0; Part Type: RESISTOR; SMT: YES
R362 = R_v2: ANOVO DESCRIPTION: RES;470 ,1/16W ,5% ,0402 ,SMT; ANOVO PART NUMBER: 271040471301; POWER: 1/16w; Part Type: RESISTOR
R452 R454 = R_v2: ANOVO DESCRIPTION: RES;100K ,1/16W ,5% ,0402 ,SMT; ANOVO PART NUMBER: 271040104301; Part Type: RESISTOR
R599 = R_v2: ANOVO DESCRIPTION: RES;56 ,1/10W ,5% ,0603 ,SMT; ANOVO PART NUMBER: 271071560301; BACKSIDE: NO; Part Type: RESISTOR; SMT: YES
R800 = R_v2: ANOVO DESCRIPTION: RES;33 ,1/16W ,5% ,0402 ,SMT; ANOVO PART NUMBER: 271040330301; POWER: 1/16W; Part Type: RESISTOR
C459 = CAP_NP: ANOVO DESCRIPTION: CAP;180P ,50V ,5% ,0402 ,NPO ,SMT; ANOVO PART NUMBER: 272045181101; BACKSIDE: 0; Part Type: CCAP; SMT: YES
C550 C598 = CAP_NP: ANOVO DESCRIPTION: CAP;0.1U ,25V ,10% ,0603 ,X7R ,SMT; ANOVO PART NUMBER: 272074104201; BACKSIDE: 0; Part Type: CCAP; SMT: YES
C567 = CAP_NP: ANOVO DESCRIPTION: CAP;2.2U ,6.3V ,10% ,0402 ,X7R ,SMT; ANOVO PART NUMBER: 272041225201
CN333-CN336 = CAP_8P4C_0: SMT: YES; anovo description: CP;180P*4,8P,50V ,10%,0612,X7R,SMT; anovo part number: 272615181201
PD1 = DIODE: ANOVO DESCRIPTION: DIODE;TCLL4148,100V,150MA,3.5*1.5MM,SMT; ANOVO PART NUMBER: 288104148001; BACKSIDE: 0; Part Type: FAST; SMT: YES; Datasheet: \\Rdserver\norcocis\datasheet\DIODE\vishay\LS4148.PDF
R150 = R_v2: ANOVO DESCRIPTION: RES;1M ,1/16W ,5% ,0402 ,SMT; ANOVO PART NUMBER: 271040105301; BACKSIDE: 0; Part Type: RESISTOR; SMT: YES
R151 = R_v2: ANOVO DESCRIPTION: RES;430 ,1/10W ,1% ,0603 ,SMT; ANOVO PART NUMBER: 271071431101; BACKSIDE: 0; Part Type: RESISTOR; SMT: YES
R391 R536 R548 R561 R579 = R_v2: ANOVO DESCRIPTION: RES;2K ,1/16W ,5% ,0402 ,SMT; ANOVO PART NUMBER: 271040202301; Part Type: RESISTOR
R475 R580 R588 R589 = R_v2: ANOVO DESCRIPTION: RES;0 ,1/16W ,5% ,0402 ,SMT; ANOVO PART NUMBER: 271040000301; BACKCOMP: YES; BACKSIDE: YES; DUMMY: Not stuff; ID: 0; Part Type: RESISTOR; SMT: YES
R479 = R_v2: ANOVO DESCRIPTION: RES;11K ,1/10W ,1% ,0603 ,SMT; ANOVO PART NUMBER: 271071113101; BACKSIDE: 0; Part Type: RESISTOR; SMT: YES
R559 R581 = R_v2: ANOVO DESCRIPTION: RES;100 ,1/16W ,1% ,0402 ,SMT; ANOVO PART NUMBER: 271040101101
R582 R584 = R_v2: ANOVO DESCRIPTION: RES;39,1/10W ,5% ,0603 ,SMT; ANOVO PART NUMBER: 271071390301
RN19 RN20 RN23 RN24 = RI-8P: 1ST PART FIELD: 8P1206; ANOVO DESCRIPTION: RP;2.2K*4 ,8P ,1/16W ,5% ,0612 ,SMT; ANOVO PART NUMBER: 271610222301; Package  Field: 8P1206
U31 = TC7SH08FU_0: ANOVO DESCRIPTION: IC,74LVC1G00,NAND,SC70,PHLIPIS; ANOVO PART NUMBER: 282077410001
U55 U56 = PI5V330_0: Part Number: 1410000702

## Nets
3.3V1: J2.C10(3.3V1)
3.3V2: J2.C18(3.3V2)
3.3V3: J2.D25(3.3V3)
3.3V4: J2.A15(3.3V4)
3.3V5: J2.A17(3.3V5)
3.3V6: J2.A19(3.3V6)
3.3V7: J2.A21(3.3V7)
3.3V8: J2.A23(3.3V8)
+3V: C620.1 C621.1 POWER_SEL2.3 Q9.1(GATE) R300.2 R301.2 R377.1 R393.2 R451.1 R536.2 R548.2 R597.1 R672.2 R673.2 U20.10(VCC1) U20.20(VCC2) U24.1(VDD1) U24.26(VDD2) U24.34(VDD3) U24.40(VDD4) U24.51(VDD5) U24.53(VDD6) U24.56(VDD7) U24.62(VDD8) U24.69(VDD9) U24.75(VDD10) U24.81(VDD11) U24.91(VDD12) U24.97(VDD13) U24.105(VDD14) U24.108(VDD15) U24.114(VDD16) U24.120(VDD17) U24.124(P_VIO) U24.131(VDD18) U24.139(VDD19) U24.145(VDD20) U24.151(VDD21) U24.155(VDD22) U24.157(VDD23) U24.163(VDD24) U24.170(VDD25) U24.178(VDD26) U24.184(VDD27) U24.190(VDD28) U24.196(VDD29) U24.202(VDD30) U24.208(VDD31) U81.5(VCC) U82.5(VCC) ; also on sheet 4 9 10 12 15 16 17 18 19 20 21 22 23 31 32 34 35 41
+3V_DUAL: R347.1 ; also on sheet 14 15 16 17 18 19 20 21 31 33 34 38 40 41
+5V: C412.1 C417.1 C420.2 C431.2 C437.1 C438.1 C550.2 C598.2 FB17.2 FB18.2 PD1.1(A) POWER_SEL2.1 R150.2 R302.2 R346.2 R358.1 R394.1 R414.2 R415.2 R561.2 R579.2 U14.5(VCC) U19.5(VCC) U31.5(VCC) U55.16(VCC) U56.16(VCC) U57.5(VCC) U58.5(VCC) ; also on sheet 18 21 22 23 29 30 31 32 33 34 35 40
+5V_CPCI: J2.A1(VCC1) J2.A25(VCC5) J2.B2(VCC2) J2.B24(VCC4) J2.D3(Long_VCC2) J2.D23(Long_VCC1) J2.E1(VCC3) J2.E25(VCC6) ; also on sheet 34
+5V_DUAL: R362.1 R413.1 ; also on sheet 18 21 30 31 33 34
+12V_CPCI: IDE_SLIM1.44 J2.D1(+12V) R452.1 R479.2 SATA3.6 ; also on sheet 21 32 34
GND: C48.2 C412.2 C413.1 C414.2 C415.2 C416.1 C417.2 C421.1 C432.2 C433.2 C436.1 C437.2 C438.2 C459.1 C545.2 C550.1 C598.1 C602.2 C603.2 C604.2 C620.2 C621.2 CN333.2(C12) CN333.4(C22) CN333.6(C32) CN333.8(C42) CN334.2(C12) CN334.4(C22) CN334.6(C32) CN334.8(C42) CN335.2(C12) CN335.4(C22) CN335.6(C32) CN335.8(C42) CN336.2(C12) CN336.4(C22) CN336.6(C32) CN336.8(C42) IDE_SLIM1.2 IDE_SLIM1.19 IDE_SLIM1.22 IDE_SLIM1.24 IDE_SLIM1.26 IDE_SLIM1.30 IDE_SLIM1.40 IDE_SLIM1.43 J2.B8(GND7) J2.B10(GND6) J2.B18(GND5) J2.B20(GND4) J2.B22(GND3) J2.D5(Long_GND6) J2.D7(Long_GND5) J2.D9(Long_GND4) J2.D11(Long_GND3) J2.D17(Long_GND2) J2.D19(Long_GND1) J2.F1(GND29) J2.F2(GND28) J2.F3(GND27) J2.F4(GND26) J2.F5(GND25) J2.F6(GND24) J2.F7(GND23) J2.F8(GND22) J2.F9(GND21) J2.F10(GND20) J2.F11(GND19) J2.F12(GND30) J2.F13(GND2) J2.F14(GND1) J2.F15(GND18) J2.F16(GND17) J2.F17(GND16) J2.F18(GND15) J2.F19(GND14) J2.F20(GND13) J2.F21(GND12) J2.F22(GND11) J2.F23(GND10) J2.F24(GND9) J2.F25(GND8) J3.B1(GND2) J3.B3(GND3) J3.B5(GND4) J3.B7(GND5) J3.B9(GND6) J3.B11(GND7) J3.B13(GND8) J3.B20(GND12) J3.B21(GND13) J3.D4(GND14) J3.D6(GND15) J3.D8(GND16) J3.D10(GND17) J3.D12(GND18) J3.D14(GND19) J3.D16(GND20) J3.D18(GND21) J3.D20(GND22) J3.F1(GND23) J3.F2(GND24) J3.F3(GND25) J3.F4(GND26) J3.F5(GND27) J3.F6(GND28) J3.F7(GND29) J3.F8(GND30) J3.F9(GND31) J3.F10(GND32) J3.F11(GND33) J3.F12(GND34) J3.F13(GND35) J3.F14(GND36) J3.F15(GND37) J3.F16(GND38) J3.F17(GND39) J3.F18(GND40) J3.F19(GND41) J3.F20(GND42) J3.F21(GND43) J3.F22(GND44) J4.A19(RSV15) J4.B19(RSV30) J4.C15(GND20) J4.C16(GND21) J4.C17(GND22) J4.C18(GND23) J4.C19(RSV45) J4.D19(RSV60) J4.E19(RSV75) J4.F1(GND1) J4.F2(GND2) J4.F3(GND3) J4.F4(GND4) J4.F5(GND5) J4.F6(GND6) J4.F7(GND7) J4.F8(GND8) J4.F9(GND9) J4.F10(GND10) J4.F11(GND11) J4.F12(GND12) J4.F13(GND13) J4.F14(GND14) J4.F15(GND15) J4.F16(GND16) J4.F17(GND17) J4.F18(GND18) J4.F19(GND19) POWER_SW2.2 PQ2.2(SOURCE) PQ3.2(SOURCE) PQ4.2(SOURCE) Q11.2(E) Q13.2(E) Q14.2(E) R306.1 R315.2 R317.2 R361.2 R395.1 R396.1 R397.1 R398.1 R399.1 R400.1 R401.1 R409.1 R410.1 R412.1 R439.2 R454.2 R574.1 R587.1 R625.2 SATA3.7 U14.8(GND) U19.8(GND) U20.2(GND) U20.12(GND) U24.12(GND1) U24.20(GND2) U24.23(S_CFN#) U24.31(GND3) U24.37(GND4) U24.48(GND5) U24.52(GND6) U24.54(GND7) U24.59(GND8) U24.66(GND9) U24.72(GND10) U24.78(GND11) U24.86(GND12) U24.94(GND13) U24.100(GND14) U24.104(GND15) U24.106(GND16) U24.111(GND17) U24.117(GND18) U24.123(GND19) U24.136(GND20) U24.142(GND21) U24.148(GND22) U24.156(GND23) U24.166(GND24) U24.174(GND25) U24.181(GND26) U24.187(GND27) U24.193(GND28) U24.199(GND29) U24.205(GND30) U31.3(GND) U55.8(GND) U55.12(YD) U55.15(E#) U56.8(GND) U56.15(E#) U57.3(GND) U58.3(GND) U81.3(GND) U82.3(GND) ; also on sheet 4 5 6 7 9 10 11 12 13 14 15 16 17 18 19 20 21 22 23 29 30 31 32 33 34 35 36 37 38 39 40 41
GND1: J3.A19(GND1)
GND9: J3.B15(GND9)
GND10: J3.B17(GND10)
GND11: J3.B19(GND11)
+CPCI_VIO: J2.C4(Long_V(I/O)1) J2.C8(V(I/O)1) J2.C16(V(I/O)2) J2.C20(V(I/O)3) J2.C24(Long_V(I/O)2) J3.A4(VIO1) J3.C5(VIO2) J3.C7(VIO3) J3.C9(VIO4) J3.C11(VIO5) J3.C13(VIO6) R416.1 R417.2 R418.2 R419.2 R622.2 R623.2 R624.2 R626.1 RP27.1 RP27.3 RP27.5 RP27.7 RP33.5(R8) RP33.6(R6) RP33.7(R4) RP33.8(R2) RP34.5(R8) RP34.6(R6) RP34.7(R4) RP34.8(R2) RP35.1(R1) RP35.2(R3) RP35.3(R5) RP35.4(R7) RP36.5(R8) RP36.6(R6) RP36.7(R4) RP36.8(R2) RP37.1(R1) RP37.2(R3) RP37.3(R5) RP37.4(R7) RP38.5(R8) RP38.6(R6) RP38.7(R4) RP38.8(R2) RP40.1 RP40.3 RP40.5 RP40.7 RP41.1 RP41.3 RP41.5 RP41.7 RP42.1 RP42.3 RP42.5 RP42.7 RP43.1 RP43.3 RP43.5 RP43.7 RP44.1 RP44.3 RP44.5 RP44.7 RP45.1 RP45.3 RP45.5 RP45.7 RP46.1 RP46.3 RP46.5 RP46.7 RP47.1 RP47.3 RP47.5 RP47.7 U24.135(S_VIO)
ACK64#: R406.1 R415.1
ACZ_SPKR: R385.1 ; also on sheet 17 23
AD0: U24.122(P_AD0) ; also on sheet 16
AD1: U24.121(P_AD1) ; also on sheet 16
AD2: U24.119(P_AD2) ; also on sheet 16
AD3: U24.118(P_AD3) ; also on sheet 16
AD4: U24.116(P_AD4) ; also on sheet 16
AD5: U24.115(P_AD5) ; also on sheet 16
AD6: U24.113(P_AD6) ; also on sheet 16
AD7: U24.112(P_AD7) ; also on sheet 16
AD8: U24.109(P_AD8) ; also on sheet 16
AD9: U24.107(P_AD9) ; also on sheet 16
AD10: U24.101(P_AD10) ; also on sheet 16
AD11: U24.99(P_AD11) ; also on sheet 16
AD12: U24.98(P_AD12) ; also on sheet 16
AD13: U24.96(P_AD13) ; also on sheet 16
AD14: U24.95(P_AD14) ; also on sheet 16
AD15: U24.93(P_AD15) ; also on sheet 16
AD16: U24.77(P_AD16) ; also on sheet 16
AD17: U24.76(P_AD17) ; also on sheet 16
AD18: U24.74(P_AD18) ; also on sheet 16
AD19: R404.2 U24.73(P_AD19) ; also on sheet 16
AD20: U24.71(P_AD20) ; also on sheet 16
AD21: U24.70(P_AD21) ; also on sheet 16
AD22: U24.68(P_AD22) ; also on sheet 16
AD23: U24.67(P_AD23) ; also on sheet 16
AD24: U24.63(P_AD24) ; also on sheet 16
AD25: U24.61(P_AD25) ; also on sheet 16
AD26: U24.60(P_AD26) ; also on sheet 16
AD27: U24.58(P_AD27) ; also on sheet 16
AD28: U24.57(P_AD28) ; also on sheet 16
AD29: U24.55(P_AD29) ; also on sheet 16
AD30: U24.50(P_AD30) ; also on sheet 16
AD31: U24.49(P_AD31) ; also on sheet 16
CBE#0: U24.110(P_CBE#0) ; also on sheet 16
CBE#1: U24.92(P_CBE#1) ; also on sheet 16
CBE#2: U24.79(P_CBE#2) ; also on sheet 16
CBE#3: U24.64(P_CBE#3) ; also on sheet 16
COM1_CTS0-: U19.24(RI5) ; also on sheet 29
COM1_DCD0-: U19.16(RI2) ; also on sheet 29
COM1_DSR0-: U19.15(RI1) ; also on sheet 29
COM1_DTR0-: U19.4(TX3) ; also on sheet 29
COM1_MODE: U19.25(RS232/RS485) ; also on sheet 22
COM1_RTS0-: U19.7(TX2) ; also on sheet 29
COM1_RX: U19.27(TI1) ; also on sheet 21
COM1_RX0: U19.6(TX1) ; also on sheet 29
COM1_TX: U19.21(RX3) ; also on sheet 21
COM1_TX0: U19.17(RI3) ; also on sheet 29
COM2_CTS-: U14.19(RX1) ; also on sheet 21
COM2_CTS_R: U14.15(RI1) ; also on sheet 29
COM2_DCD-: U14.23(RX5) ; also on sheet 21
COM2_DCD_R: U14.24(RI5) ; also on sheet 29
COM2_DSR-: U14.20(RX2) ; also on sheet 21
COM2_DSR_R: U14.16(RI2) ; also on sheet 29
COM2_DTR-: U14.1(TI3) ; also on sheet 21
COM2_DTR_R: U14.4(TX3) ; also on sheet 29
COM2_MODE: U14.25(RS232/RS485) ; also on sheet 22
COM2_RI-: U14.22(RX4) ; also on sheet 21
COM2_RS232_RX: U14.6(TX1) ; also on sheet 29
COM2_RS232_TX: U14.17(RI3) ; also on sheet 29
COM2_RTS-: R573.2 U14.28(TI2) ; also on sheet 21
COM2_RTS_R: U14.7(TX2) ; also on sheet 29
CRT_BLU_RIO: U55.11(I0C) ; also on sheet 30
CRT_DCLK_1: R559.2 U56.12(YD)
CRT_DDAT_1: R581.2 U56.9(YC)
CRT_GRN_RIO: U55.5(I0B) ; also on sheet 30
CRT_HSYNC_1: R582.2 U56.4(YA)
CRT_HSYNC_RIO: U56.2(I0A) ; also on sheet 30
CRT_RED_RIO: U55.2(I0A) ; also on sheet 30
CRT_VSYNC_1: R584.2 U56.7(YB)
CRT_VSYNC_RIO: U56.5(I0B) ; also on sheet 30
CRTDCLK: Q8.3(DRAIN) R475.1 R536.1 ; also on sheet 10
CRTDDAT: Q10.3(DRAIN) R548.1 R580.1 ; also on sheet 10
CRTHSYNC: R583.1 ; also on sheet 10
CRTVSYNC: R585.1 ; also on sheet 10
CTS0-: U19.23(RX5) ; also on sheet 21
DCD0-: U19.20(RX2) ; also on sheet 21
DDC_CLK_RIO: U56.14(I0D) ; also on sheet 30
DDC_DAT_RIO: U56.11(I0C) ; also on sheet 30
DEVSEL#: U24.84(P_DEVSEL#) ; also on sheet 16
DMG_SELF: R598.2 SATA3.8 ; also on sheet 29
DSR0-: U19.19(RX1) ; also on sheet 21
DTR0-: U19.1(TI3) ; also on sheet 21
FRAME#: U24.80(P_FRAME#) ; also on sheet 16
FRONT_BLUE: U55.10(I1C) ; also on sheet 40
FRONT_DDCCLK_CN: U56.13(I1D) ; also on sheet 40
FRONT_DDCDAT_CN: U56.10(I1C) ; also on sheet 40
FRONT_GREEN: U55.6(I1B) ; also on sheet 40
FRONT_HSYNC_CN: U56.3(I1A) ; also on sheet 40
FRONT_RED: U55.3(I1A) ; also on sheet 40
FRONT_VSYNC_CN: U56.6(I1B) ; also on sheet 40
GNT2#: U24.46(P_GNT#) ; also on sheet 16
HDD_VDD: C413.2 C414.1 C415.1 C416.2 FB17.1 IDE_SLIM1.41 IDE_SLIM1.42 R311.2
IDE_MODE_SEL: IDE_SLIM1.28 R315.1 ; also on sheet 22
IDE_SIOCS16#: IDE_SLIM1.32
IDELED#: IDE_SLIM1.39 ; also on sheet 30
IDERST#: IDE_SLIM1.1 Q9.3(DRAIN) R302.1
INTE#: RP26.3 ; also on sheet 16
INTF#: RP26.5 ; also on sheet 16
INTG#: RP26.7 ; also on sheet 16
INTH#: RP26.1 ; also on sheet 16
IRDY#: U24.82(P_IRDY#) ; also on sheet 16
IRQ14: IDE_SLIM1.31 R300.1 ; also on sheet 15
J1_PCIXCAP: J2.B16(PCIXCAP) R412.2
J1AD0: J2.D24(PAD0) RP18.2
J1AD1: J2.A24(PAD1) RP18.4
J1AD2: J2.E23(PAD2) RP16.7
J1AD3: J2.C23(PAD3) RP18.6
J1AD4: J2.B23(PAD4) RP18.8
J1AD5: J2.E22(PAD5) RP16.5
J1AD6: J2.D22(PAD6) RP16.3
J1AD7: J2.A22(PAD7) RP16.1
J1AD8: J2.C21(PAD8) RP19.2
J1AD9: J2.B21(PAD9) RP19.6
J1AD10: J2.E20(PAD10) RP19.8
J1AD11: J2.D20(PAD11) RP20.1
J1AD12: J2.A20(PAD12) RP20.3
J1AD13: J2.E19(PAD13) RP20.7
J1AD14: J2.C19(PAD14) RP20.5
J1AD15: J2.B19(PAD15) RP29.2
J1AD16: J2.C11(PAD16) RP17.8
J1AD17: J2.B11(PAD17) RP17.6
J1AD18: J2.A11(PAD18) RP17.4
J1AD19: J2.E10(PAD19) RP17.2
J1AD20: J2.D10(PAD20) RP22.8
J1AD21: J2.A10(PAD21) RP22.6
J1AD22: J2.E9(PAD22) RP22.4
J1AD23: J2.C9(PAD23) RP22.2
J1AD24: J2.E8(PAD24) RP24.8
J1AD25: J2.D8(PAD25) RP24.6
J1AD26: J2.A8(PAD26) RP24.4
J1AD27: J2.E7(PAD27) RP24.2
J1AD28: J2.C7(PAD28) RP25.8
J1AD29: J2.B7(PAD29) RP25.6
J1AD30: J2.A7(PAD30) RP25.4
J1AD31: J2.E6(PAD31) RP25.2
J1CBE0: J2.E21(C/BE0#) RP19.4
J1CBE1: J2.E18(C/BE1#) RP29.4
J1CBE2: J2.E11(C/BE2#) RP32.3
J1CBE3: J2.A9(C/BE3#) RP32.1
J1DEVSEL#: J2.A16(DEVSEL#) RP31.3
J1FRAME#: J2.B15(FRAME#) RP32.5
J1INTA: J2.A3(INTA#) RP26.4
J1INTB: J2.B3(INTB#) RP26.6
J1INTC: J2.C3(INTC#) RP26.8
J1INTD: J2.E3(INTD#) RP26.2
J1IRDY#: J2.C15(IRDY#) RP32.7
J1LOCK#: J2.E16(LOCK#) RP31.7
J1PAR: J2.D18(PAR) R405.2
J1PERR#: J2.E17(PERR#) RP29.8
J1SERR#: J2.A18(SERR#) RP29.6
J1STOP#: J2.D16(STOP#) RP31.5
J1TRDY#: J2.E15(TRDY#) RP31.1
J2_AD32: J3.E14(AD32) RP27.8
J2_AD33: J3.C14(AD33) RP27.6
J2_AD34: J3.B14(AD34) RP27.4
J2_AD35: J3.A14(AD35) RP27.2
J2_AD36: J3.E13(AD36) RP40.6
J2_AD37: J3.D13(AD37) RP40.4
J2_AD38: J3.A13(AD38) RP40.2
J2_AD39: J3.E12(AD39) RP41.4
J2_AD40: J3.C12(AD40) RP41.2
J2_AD41: J3.B12(AD41) RP40.8
J2_AD42: J3.A12(AD42) RP41.6
J2_AD43: J3.E11(AD43) RP42.4
J2_AD44: J3.D11(AD44) RP42.2
J2_AD45: J3.A11(AD45) RP41.8
J2_AD46: J3.E10(AD46) RP42.8
J2_AD47: J3.C10(AD47) RP42.6
J2_AD48: J3.B10(AD48) RP43.2
J2_AD49: J3.A10(AD49) RP43.4
J2_AD50: J3.E9(AD50) RP43.6
J2_AD51: J3.D9(AD51) RP43.8
J2_AD52: J3.A9(AD52) RP44.2
J2_AD53: J3.E8(AD53) RP44.4
J2_AD54: J3.C8(AD54) RP44.6
J2_AD55: J3.B8(AD55) RP44.8
J2_AD56: J3.A8(AD56) RP45.2
J2_AD57: J3.E7(AD57) RP45.4
J2_AD58: J3.D7(AD58) RP45.6
J2_AD59: J3.A7(AD59) RP45.8
J2_AD60: J3.E6(AD60) RP46.2
J2_AD61: J3.C6(AD61) RP46.4
J2_AD62: J3.B6(AD62) RP46.6
J2_AD63: J3.A6(AD63) RP47.2
J2_CBE4: J3.D5(C/BE4#) RP46.8
LAD0/FWH0: U20.15(LAD0) ; also on sheet 15 21
LAD1/FWH1: U20.16(LAD1) ; also on sheet 15 21
LAD2/FWH2: U20.17(LAD2) ; also on sheet 15 21
LAD3/FWH3: U20.18(LAD3) ; also on sheet 15 21
LAN1_ACT#: J4.A13(RSV13) ; also on sheet 19
LAN1_LNK#: J4.A12(RSV12) J4.D12(RSV57) R672.1 R673.1 U81.4(OUT) U82.4(OUT)
LAN1_LNK_100#: J4.B12(RSV27) U81.2(INA) ; also on sheet 19
LAN1_LNK_1000#: J4.B13(RSV28) U81.1(INB) ; also on sheet 19
LAN1_TRD0N: J4.B18(LPA_DA-) ; also on sheet 19
LAN1_TRD0P: J4.A18(LPA_DA+) ; also on sheet 19
LAN1_TRD1N: J4.B17(LPA_DB-) ; also on sheet 19
LAN1_TRD1P: J4.A17(LPA_DB+) ; also on sheet 19
LAN1_TRD2N: J4.E18(LPA_DC-) ; also on sheet 19
LAN1_TRD2P: J4.D18(LPA_DC+) ; also on sheet 19
LAN1_TRD3N: J4.E17(LPA_DD-) ; also on sheet 19
LAN1_TRD3P: J4.D17(LPA_DD+) ; also on sheet 19
LAN2_ACT#: J4.D13(RSV58) ; also on sheet 20
LAN2_LNK_100#: J4.E12(RSV72) U82.2(INA) ; also on sheet 20
LAN2_LNK_1000#: J4.E13(RSV73) U82.1(INB) ; also on sheet 20
LAN2_TRD0N: J4.B16(LPB_DA-) ; also on sheet 20
LAN2_TRD0P: J4.A16(LPB_DA+) ; also on sheet 20
LAN2_TRD1N: J4.B15(LPB_DB-) ; also on sheet 20
LAN2_TRD1P: J4.A15(LPB_DB+) ; also on sheet 20
LAN2_TRD2N: J4.E16(LPB_DC-) ; also on sheet 20
LAN2_TRD2P: J4.D16(LPB_DC+) ; also on sheet 20
LAN2_TRD3N: J4.E15(LPB_DD-) ; also on sheet 20
LAN2_TRD3P: J4.D15(LPB_DD+) ; also on sheet 20
LCD_ON: PQ2.1(GATE) R454.1 ; also on sheet 10
LCDVCC: C545.1 C603.1 C604.1 PQ1.2(SOURCE) R599.1 ; also on sheet 30
LFRAME#/FWH4: U20.14(LFRAME#) ; also on sheet 15 21
LONG_3.3V1: J2.C22(Long_3.3V1)
LONG_3.3V2: J2.C6(Long_3.3V2)
LPC_CLK_P80: U20.13(PCICLK) ; also on sheet 4
LPC_SPKR: R360.1
PACK#: CN336.7(C41) J4.B5(RSV20) RN23.1 ; also on sheet 21
PAFD#: CN334.1(C11) J4.B7(RSV22) RN24.4(7) ; also on sheet 21
PAR: U24.90(P_PAR) ; also on sheet 16
PBUSY: CN336.3(C21) J4.A6(RSV6) RN23.3(5) ; also on sheet 21
PCI_CLK_SLOTS: U24.45(P_CLOCK) ; also on sheet 4
PCIRST#: U24.43(P_RESET#) ; also on sheet 16
PCLK_SMB: R334.2 ; also on sheet 4 17
PDA0: IDE_SLIM1.35 ; also on sheet 15
PDA1: IDE_SLIM1.33 ; also on sheet 15
PDA2: IDE_SLIM1.36 ; also on sheet 15
PDAT_SMB: R333.2 ; also on sheet 4 17
PDCS1#: IDE_SLIM1.37 ; also on sheet 15
PDCS3#: IDE_SLIM1.38 ; also on sheet 15
PDD0: IDE_SLIM1.17 ; also on sheet 15
PDD1: IDE_SLIM1.15 ; also on sheet 15
PDD2: IDE_SLIM1.13 ; also on sheet 15
PDD3: IDE_SLIM1.11 ; also on sheet 15
PDD4: IDE_SLIM1.9 ; also on sheet 15
PDD5: IDE_SLIM1.7 ; also on sheet 15
PDD6: IDE_SLIM1.5 ; also on sheet 15
PDD7: IDE_SLIM1.3 R317.1 ; also on sheet 15
PDD8: IDE_SLIM1.4 ; also on sheet 15
PDD9: IDE_SLIM1.6 ; also on sheet 15
PDD10: IDE_SLIM1.8 ; also on sheet 15
PDD11: IDE_SLIM1.10 ; also on sheet 15
PDD12: IDE_SLIM1.12 ; also on sheet 15
PDD13: IDE_SLIM1.14 ; also on sheet 15
PDD14: IDE_SLIM1.16 ; also on sheet 15
PDD15: IDE_SLIM1.18 ; also on sheet 15
PDDACK#: IDE_SLIM1.29 R311.1 ; also on sheet 15
PDDREQ: IDE_SLIM1.21 ; also on sheet 15
PDIAG: IDE_SLIM1.34 R306.2 ; also on sheet 17
PDIOR#: IDE_SLIM1.25 ; also on sheet 15
PDIOW#: IDE_SLIM1.23 ; also on sheet 15
PERR#: U24.88(P_PERR#) ; also on sheet 16
PERROR#: CN334.5(C31) J4.A8(RSV8) RN24.2(3) ; also on sheet 21
PINIT#: CN334.3(C21) J4.B8(RSV23) RN24.3(5) ; also on sheet 21
PIORDY: IDE_SLIM1.27 R301.1 ; also on sheet 15
PIOVCC: PD1.2(C) R391.2 RN19.5(8) RN19.6 RN19.7(4) RN19.8(2) RN20.5(8) RN20.6 RN20.7(4) RN20.8(2) RN23.5(8) RN23.6 RN23.7(4) RN23.8(2) RN24.5(8) RN24.6 RN24.7(4) RN24.8(2)
PLOCK#: U24.87(P_LOCK) ; also on sheet 16
PLTRST#: R304.1 U20.19(PCIRST#) ; also on sheet 16 19 20 21 35
PPD0: CN335.1(C11) J4.B1(RSV16) RN20.4(7) ; also on sheet 21
PPD1: CN335.5(C31) J4.A2(RSV2) RN20.2(3) ; also on sheet 21
PPD2: CN335.3(C21) J4.B2(RSV17) RN20.3(5) ; also on sheet 21
PPD3: CN335.7(C41) J4.A3(RSV3) RN20.1 ; also on sheet 21
PPD4: CN333.7(C41) J4.B3(RSV18) RN19.1 ; also on sheet 21
PPD5: CN333.5(C31) J4.A4(RSV4) RN19.2(3) ; also on sheet 21
PPD6: CN333.3(C21) J4.B4(RSV19) RN19.3(5) ; also on sheet 21
PPD7: CN333.1(C11) J4.A5(RSV5) RN19.4(7) ; also on sheet 21
PPE: CN336.5(C31) J4.B6(RSV21) RN23.2(3) ; also on sheet 21
PSLCT: CN336.1(C11) J4.A7(RSV7) RN23.4(7) ; also on sheet 21
PSLIN#: CN334.7(C41) J4.A9(RSV9) RN24.1 ; also on sheet 21
PSTB#: C459.2 J4.A1(RSV1) R391.1 ; also on sheet 21
PWRBTN: POWER_SW1.1 R362.2 ; also on sheet 17 21 30
PWROK: R151.2 ; also on sheet 9 17 21 31
PWROK_TST: C48.1 Q12.3(C) R150.1 R384.1 U31.2(INA)
REQ2#: U24.47(P_REQ#) ; also on sheet 16
REQ64#: R407.1 R414.1
RI0-: U19.22(RX4) ; also on sheet 21
RINGW0: U19.18(RI4) ; also on sheet 29
RINGW1_R: U14.18(RI4) ; also on sheet 29
RS232_RX: U14.27(TI1) ; also on sheet 21
RS232_TX: U14.21(RX3) ; also on sheet 21
RS485_TXEN: R597.2 U14.2(RS485_TXEN) U19.2(RS485_TXEN)
RTS0-: R586.2 U19.28(TI2) ; also on sheet 21
S_AD0: RP18.1 U24.137(S_AD0)
S_AD1: RP18.3 U24.138(S_AD1)
S_AD2: RP16.8 U24.140(S_AD2)
S_AD3: RP18.5 U24.141(S_AD3)
S_AD4: RP18.7 U24.143(S_AD4)
S_AD5: RP16.6 U24.144(S_AD5)
S_AD6: RP16.4 U24.146(S_AD6)
S_AD7: RP16.2 U24.147(S_AD7)
S_AD8: RP19.1 U24.150(S_AD8)
S_AD9: RP19.5 U24.152(S_AD9)
S_AD10: RP19.7 U24.154(S_AD10)
S_AD11: RP20.2 U24.159(S_AD11)
S_AD12: RP20.4 U24.161(S_AD12)
S_AD13: RP20.8 U24.162(S_AD13)
S_AD14: RP20.6 U24.164(S_AD14)
S_AD15: RP29.1 U24.165(S_AD15)
S_AD16: RP17.7 U24.182(S_AD16)
S_AD17: RP17.5 U24.183(S_AD17)
S_AD18: RP17.3 U24.185(S_AD18)
S_AD19: RP17.1 U24.186(S_AD19)
S_AD20: RP22.7 U24.188(S_AD20)
S_AD21: RP22.5 U24.189(S_AD21)
S_AD22: RP22.3 U24.191(S_AD22)
S_AD23: RP22.1 U24.192(S_AD23)
S_AD24: RP24.7 U24.195(S_AD24)
S_AD25: RP24.5 U24.197(S_AD25)
S_AD26: RP24.3 U24.198(S_AD26)
S_AD27: RP24.1 U24.200(S_AD27)
S_AD28: RP25.7 U24.201(S_AD28)
S_AD29: RP25.5 U24.203(S_AD29)
S_AD30: RP25.3 U24.204(S_AD30)
S_AD31: RP25.1 U24.206(S_AD31)
S_CBE#0: RP19.3 U24.149(S_CBE#0)
S_CBE#1: RP29.3 U24.167(S_CBE#1)
S_CBE#2: RP32.4 U24.180(S_CBE#2)
S_CBE#3: RP32.2 U24.194(S_CBE#3)
S_CLK0: J2.D6(CLK0) R426.2
S_CLK0_R: R426.1 U24.29(S_CLK0)
S_CLK1: J3.A1(CLK1) RP28.8
S_CLK2: J3.A2(CLK2) RP28.6
S_CLK3: J3.B2(CLK3) RP28.4
S_CLK4: J3.A3(CLK4) RP28.2
S_CLK5: J3.A20(CLK5) RP30.8
S_CLK6: J3.A21(CLK6) RP30.6
S_CLK7: R340.2 RP30.4
S_CLK7_R: J3.C20(RSV1) R340.1
S_CLK8: R341.2 R434.2
S_CLK8_R: J3.C21(RSV2) R341.1
S_CLK_FB: RP30.2 U24.21(S_CLK)
S_DEVSEL#: RP31.4 RP37.7(R4) U24.175(S_DEVSEL#)
S_FRAME#: R417.1 RP32.6 U24.179(S_FRAME#)
S_GNT#0: J2.E5(GNT0#) R419.1 U24.10(S_GNT#0)
S_GNT#1: J3.D1(GNT1#) RP38.4(R7) U24.11(S_GNT#1)
S_GNT#2: J3.D2(GNT2#) RP38.3(R5) U24.13(S_GNT#2)
S_GNT#3: J3.C3(GNT3#) RP38.2(R3) U24.14(S_GNT#3)
S_GNT#4: J3.E3(GNT4#) RP38.1(R1) U24.15(S_GNT#4)
S_GNT#5: J3.E15(GNT5#) RP36.4(R7) U24.16(S_GNT#5)
S_GNT#6: J3.E17(GNT6#) RP36.3(R5) U24.17(S_GNT#6)
S_GNT#7: R343.2 RP36.2(R3) U24.18(S_GNT#7)
S_GNT#7_R: J3.E20(RSV4) R343.1
S_GNT#8: R344.2 RP36.1(R1) U24.19(S_GNT#8)
S_GNT#8_R: J3.E21(RSV5) R344.1
S_IRDY#: RP32.8 RP37.5(R8) U24.177(S_IRDY#)
S_LOCK#: RP31.8 RP35.5(R8) U24.172(S_LOCK)
S_PAR: R405.1 U24.168(S_PAR)
S_PCIRST#: R408.1 R418.1 U24.22(S_RESET#)
S_PERR#: RP29.7 RP35.6(R6) U24.171(S_PERR#)
S_REQ#0: J2.A6(REQ0#) R416.2 RP23.8
S_REQ#1: J3.C1(REQ1#) RP23.6 RP34.4(R7)
S_REQ#2: J3.E1(REQ2#) RP23.4 RP34.3(R5)
S_REQ#3: J3.E2(REQ3#) RP23.2 RP34.2(R3)
S_REQ#4: J3.D3(REQ4#) RP21.8 RP34.1(R1)
S_REQ#5: J3.D15(REQ5#) RP21.6 RP33.4(R7)
S_REQ#6: J3.D17(REQ6#) RP21.4 RP33.3(R5)
S_REQ#7: R425.2 RP21.2 RP33.2(R3)
S_REQ#7_R: J3.D19(SMB_SCL) R334.1 R425.1
S_REQ#8: R342.2 R402.2 RP33.1(R1)
S_REQ#8_R: J3.D21(RSV3) R342.1
S_SERR#: RP29.5 RP35.7(R4) U24.169(S_SERR#)
S_STOP#: RP31.6 RP37.8(R2) U24.173(S_STOP#)
S_TRDY#: RP31.2 RP37.6(R6) U24.176(S_TRDY#)
SATA_RX2C+: SATA3.3 ; also on sheet 15
SATA_RX2C-: SATA3.4 ; also on sheet 15
SATA_TX2C+: SATA3.1 ; also on sheet 15
SATA_TX2C-: SATA3.2 ; also on sheet 15
SATA_VDD: FB18.1 SATA3.5
SERR#: U24.89(P_SERR#) ; also on sheet 16
SMB_ALERT#: R359.2 ; also on sheet 17
SPKDATA: BEEP1.2 C433.1 Q13.3(C) Q14.3(C)
STOP#: U24.85(P_STOP#) ; also on sheet 16
SYS_RST#: C567.2 R354.1 R800.2 ; also on sheet 5 17
SYS_RST_FP: C432.1 POWER_SW2.1 R800.1 ; also on sheet 29
TRDY#: U24.83(P_TRDY#) ; also on sheet 16
VGA_BLU: U55.9(YC) ; also on sheet 10
VGA_GRN: U55.7(YB) ; also on sheet 10
VGA_J_EN#: U55.1(S) U56.1(S) ; also on sheet 22
VGA_RED: U55.4(YA) ; also on sheet 10
WATCHDOG_GPO: U31.1(INB) ; also on sheet 17
WDTO: R346.1 R349.1
N41746233: Q9.2(SOURCE) R304.2
N57665563: J2.B4(HEALTHY#) R409.2
N57665621: J2.D21(M66EN) R410.2
N57666519: J2.C5(PCI_RST#) R408.2
N57666643: J2.E24(ACK64#) R406.2
N57666645: J2.B25(REQ64#) R407.2
N68193450: RP21.7 U24.5(S_REQ#4)
N68193452: RP23.1 U24.4(S_REQ#3)
N68193469: RP28.1 U24.35(S_CLK4)
N68193471: RP30.7 U24.36(S_CLK5)
N68193473: RP28.5 U24.32(S_CLK2)
N68193475: RP28.3 U24.33(S_CLK3)
N68193516: RP23.3 U24.3(S_REQ#2)
N68193518: RP23.5 U24.2(S_REQ#1)
N68193520: R402.1 U24.9(S_REQ#8)
N68193522: RP28.7 U24.30(S_CLK1)
N68193566: RP21.1 U24.8(S_REQ#7)
N68193603: RP30.1 U24.42(S_CLK9)
N68193605: RP23.7 U24.207(S_REQ#0)
N68193652: R393.1 U24.103(VDD/EE_EN#)
N68193689: RP21.3 U24.7(S_REQ#6)
N68193691: RP21.5 U24.6(S_REQ#5)
N68194131: RP30.5 U24.38(S_CLK6)
N68194397: R394.2 U24.134(TRESET#)
N70168399: BEEP1.1 R358.2
N70168549: Q13.1(B) R360.2
N78592703: R395.2 U24.158(GND/EE_PCLK)
N78592707: R398.2 U24.160(GND/EE_DATA)
N98784640: R376.2 U20.1(DGH#)
N98784647: LED2.6(S1) R372.1
N98784653: R372.2 U20.11(DGL#)
N98784655: LED2.7(LEDA) U20.3(LEDA)
N98784659: LED2.8(LEDB) U20.4(LEDB)
N98784663: LED2.3(LEDC) U20.5(LEDC)
N98784667: LED2.2(LEDD) U20.6(LEDD)
N98784671: LED2.1(LEDE) U20.7(LEDE)
N98784675: LED2.10(LEDF) U20.8(LEDF)
N98784681: LED2.4(LEDG) U20.9(LEDG)
N98784685: LED2.9(S2) R376.1
N98784691: LED2.5(DP) R377.2
N101619915: J3.C15(FAL#) R622.1
N101619917: J3.C16(DEG#) R623.1
N101619919: J3.C17(PRST#) R624.1
N101953908: J3.C2(SYSEN#) R625.1
N105317736: POWER_SW1.2 R361.1
N107079114: C567.1 Q11.3(C) R347.2
N107079124: Q11.1(B) R349.2
N107162729: Q12.1(B) R384.2
N107162749: Q12.2(E) R151.1
N107405549: J3.E19(SMB_ALERT) R359.1
N107432688: J3.C19(SMB_SDA) R333.1
N108124923: J3.C4(C/BE7#) RP47.8
N108124924: J3.E4(C/BE6#) RP47.6
N108124925: J3.A5(C/BE5#) RP47.4
N108326049: R354.2 U31.4(OUT)
N108579073: Q14.1(B) R385.2
N109834170: R434.1 U24.41(S_CLK8)
N109841265: RP30.3 U24.39(S_CLK7)
N115338961: Q8.2(SOURCE) R475.2 R559.1 R579.1
N115338972: Q10.2(SOURCE) R561.1 R580.2 R581.1
N115339030: Q8.1(GATE) Q10.1(GATE) R479.1
N115339151: R583.2 R588.1 U57.1(INB) U57.2(INA)
N115339171: R582.1 R588.2 U57.4(OUT)
N115339187: R585.2 R589.1 U58.1(INB) U58.2(INA)
N115339221: R584.1 R589.2 U58.4(OUT)
N116214190: IDE_SLIM1.20 R598.1
N119077818: R573.1 R574.2 U14.26(RXEN#)
N119077866: C418.2 U14.9(C1+)
N119077892: C421.2 U14.14(V-)
N119077894: C418.1 U14.12(C1-)
N119077898: C420.1 U14.10(V+)
N119077912: C419.2 U14.11(C2+)
N119077916: C419.1 U14.13(C2-)
N119165723: R586.1 R587.2 U19.26(RXEN#)
N119165776: C434.2 U19.9(C1+)
N119165794: C436.2 U19.14(V-)
N119165796: C434.1 U19.12(C1-)
N119165800: C431.1 U19.10(V+)
N119165814: C435.2 U19.11(C2+)
N119165818: C435.1 U19.13(C2-)
N123918426: C602.1 PQ1.1(GATE) PQ3.3(DRAIN) R452.2
N123918446: PQ2.3(DRAIN) PQ3.1(GATE) PQ4.1(GATE) R451.2
N123918529: POWER_SEL2.2 PQ1.3(DRAIN)
N123918584: PQ4.3(DRAIN) R599.2
N124629847: J2.B6(PCI_PRESENT#) R413.2 R439.1
N124710182: R396.2 U24.153(S_M66ENA)
N124710186: R397.2 U24.102(P_M66ENA)
N124710187: R404.1 U24.65(P_IDSEL)
N124710188: R401.2 U24.44(BPCCE)
N124710189: R400.2 U24.126(MSK_IN)
N124710190: R399.2 U24.125(CONFIG66)
N124969200: J3.E5(PAR64) R626.2

Not connected (* = marked no-connect by the designer): J2 A2(TCK)* A4(IPMB_PWR)* A5(BRSVP1A5)* B1(-12V)* B5(BRSVP1B5)* B9(IDSEL)* B17(IPMB_SCL)* C1(TRST#)* C2(TMS)* C17(IPMB_SDA)* C25(ENUM#)* D2(TDO)* D4(INTP)* D15(BD_SEL#)* E2(TDI)* E4(INTS)*; J3 A15(BRSV1)* A16(BRSV2)* A17(BRSV3)* A18(BRSV4)* A22(GA4)* B4(BRSV5)* B16(BRSV6)* B18(BRSV7)* B22(GA3)* C18(BRSV8)* C22(GA2)* D22(GA1)* E16(BRSV0)* E18(BRSV9)* E22(GA0)*; J4 A10(RSV10)* A11(RSV11)* A14(RSV14)* B9(RSV24)* B10(RSV25)* B11(RSV26)* B14(RSV29)* C1(RSV31)* C2(RSV32)* C3(RSV33)* C4(RSV34)* C5(RSV35)* C6(RSV36)* C7(RSV37)* C8(RSV38)* C9(RSV39)* C10(RSV40)* C11(RSV41)* C12(RSV42)* C13(RSV43)* C14(RSV44)* D1(RSV46)* D2(RSV47)* D3(RSV48)* D4(RSV49)* D5(RSV50)* D6(RSV51)* D7(RSV52)* D8(RSV53)* D9(RSV54)* D10(RSV55)* D11(RSV56)* D14(RSV59)* E1(RSV61)* E2(RSV62)* E3(RSV63)* E4(RSV64)* E5(RSV65)* E6(RSV66)* E7(RSV67)* E8(RSV68)* E9(RSV69)* E10(RSV70)* E11(RSV71)* E14(RSV74)*; RP35 8(R2)*; U14 3(RS485_TX4); U19 3(RS485_TX4); U24 24(GPIO3)* 25(GPIO2)* 27(GPIO1)* 28(GPIO0)* 127(NC1)* 128(NC2)* 129(TDI)* 130(TDO)* 132(TMS)* 133(TCK)*; U55 13(I1D)* 14(I0D)*

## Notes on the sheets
sheet 24
- SATA CN
- Mini IDE
- ON BOARD HDD INTERFACE
- 2COM RS232/422 for REAR I/O
- RS422_2_TX+
- RS422_2_TX-
- PORT 80
- RS422_2_RX+
- RS422_2_RX-
- RS422_1_TX+
- RS422_1_TX-
- RS422_1_RX+
- RS422_1_RX-
sheet 25
- FILTER FBM2125 HM330-T(4A,0.015)
- TRANSISTOR MOSFET RHU002N06(60V,200MA)
- Discharge
sheet 26
- WATCHDOG
- E#  S   RESULTS
  1   X          X
  0   0         I0
  0   1         I1
- (Default)
- PIO
sheet 28
- CPCI     J3     TYPEB
- CPCI     J2     TYPEA
